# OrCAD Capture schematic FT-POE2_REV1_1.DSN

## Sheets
1 INDEX: title: 01-Index; rev: 1.1; note: 17 HaYetsira Street; note: Yokneam Illit, Israel 2069208
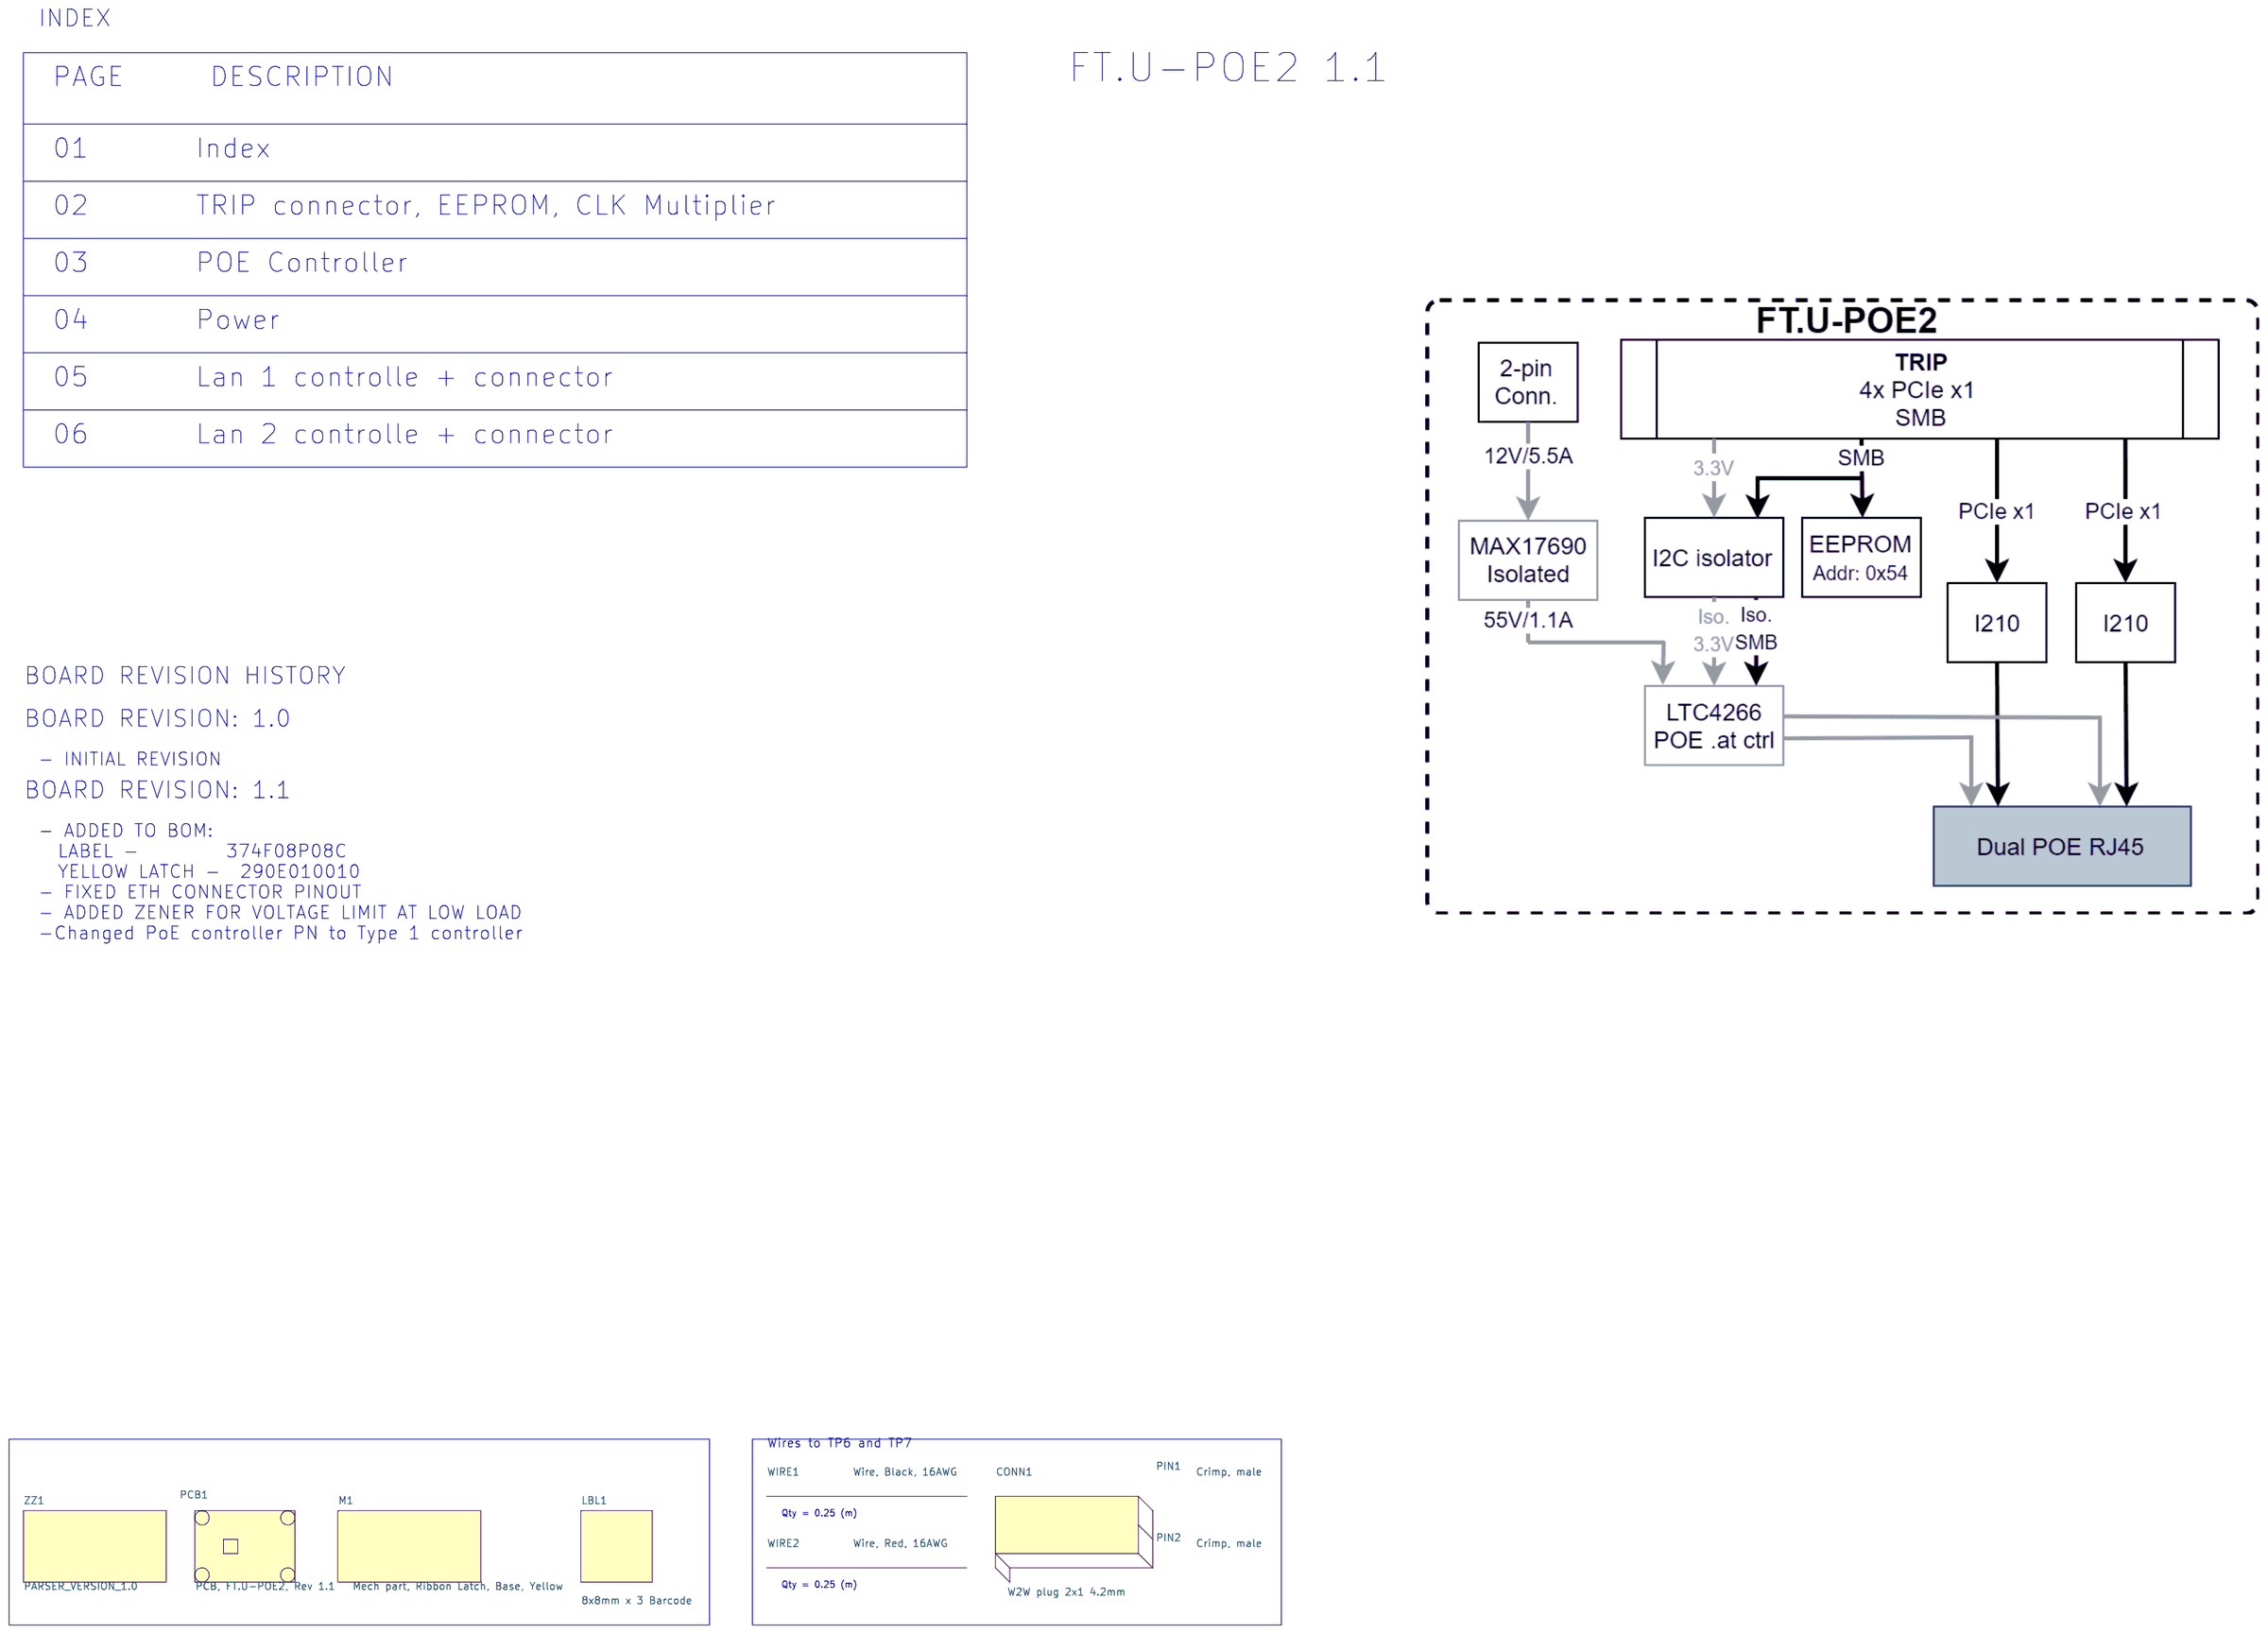
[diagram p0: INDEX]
2 TRIP/CLKMP: size A; title: 02-TRIP/CLKMP; rev: 1.0
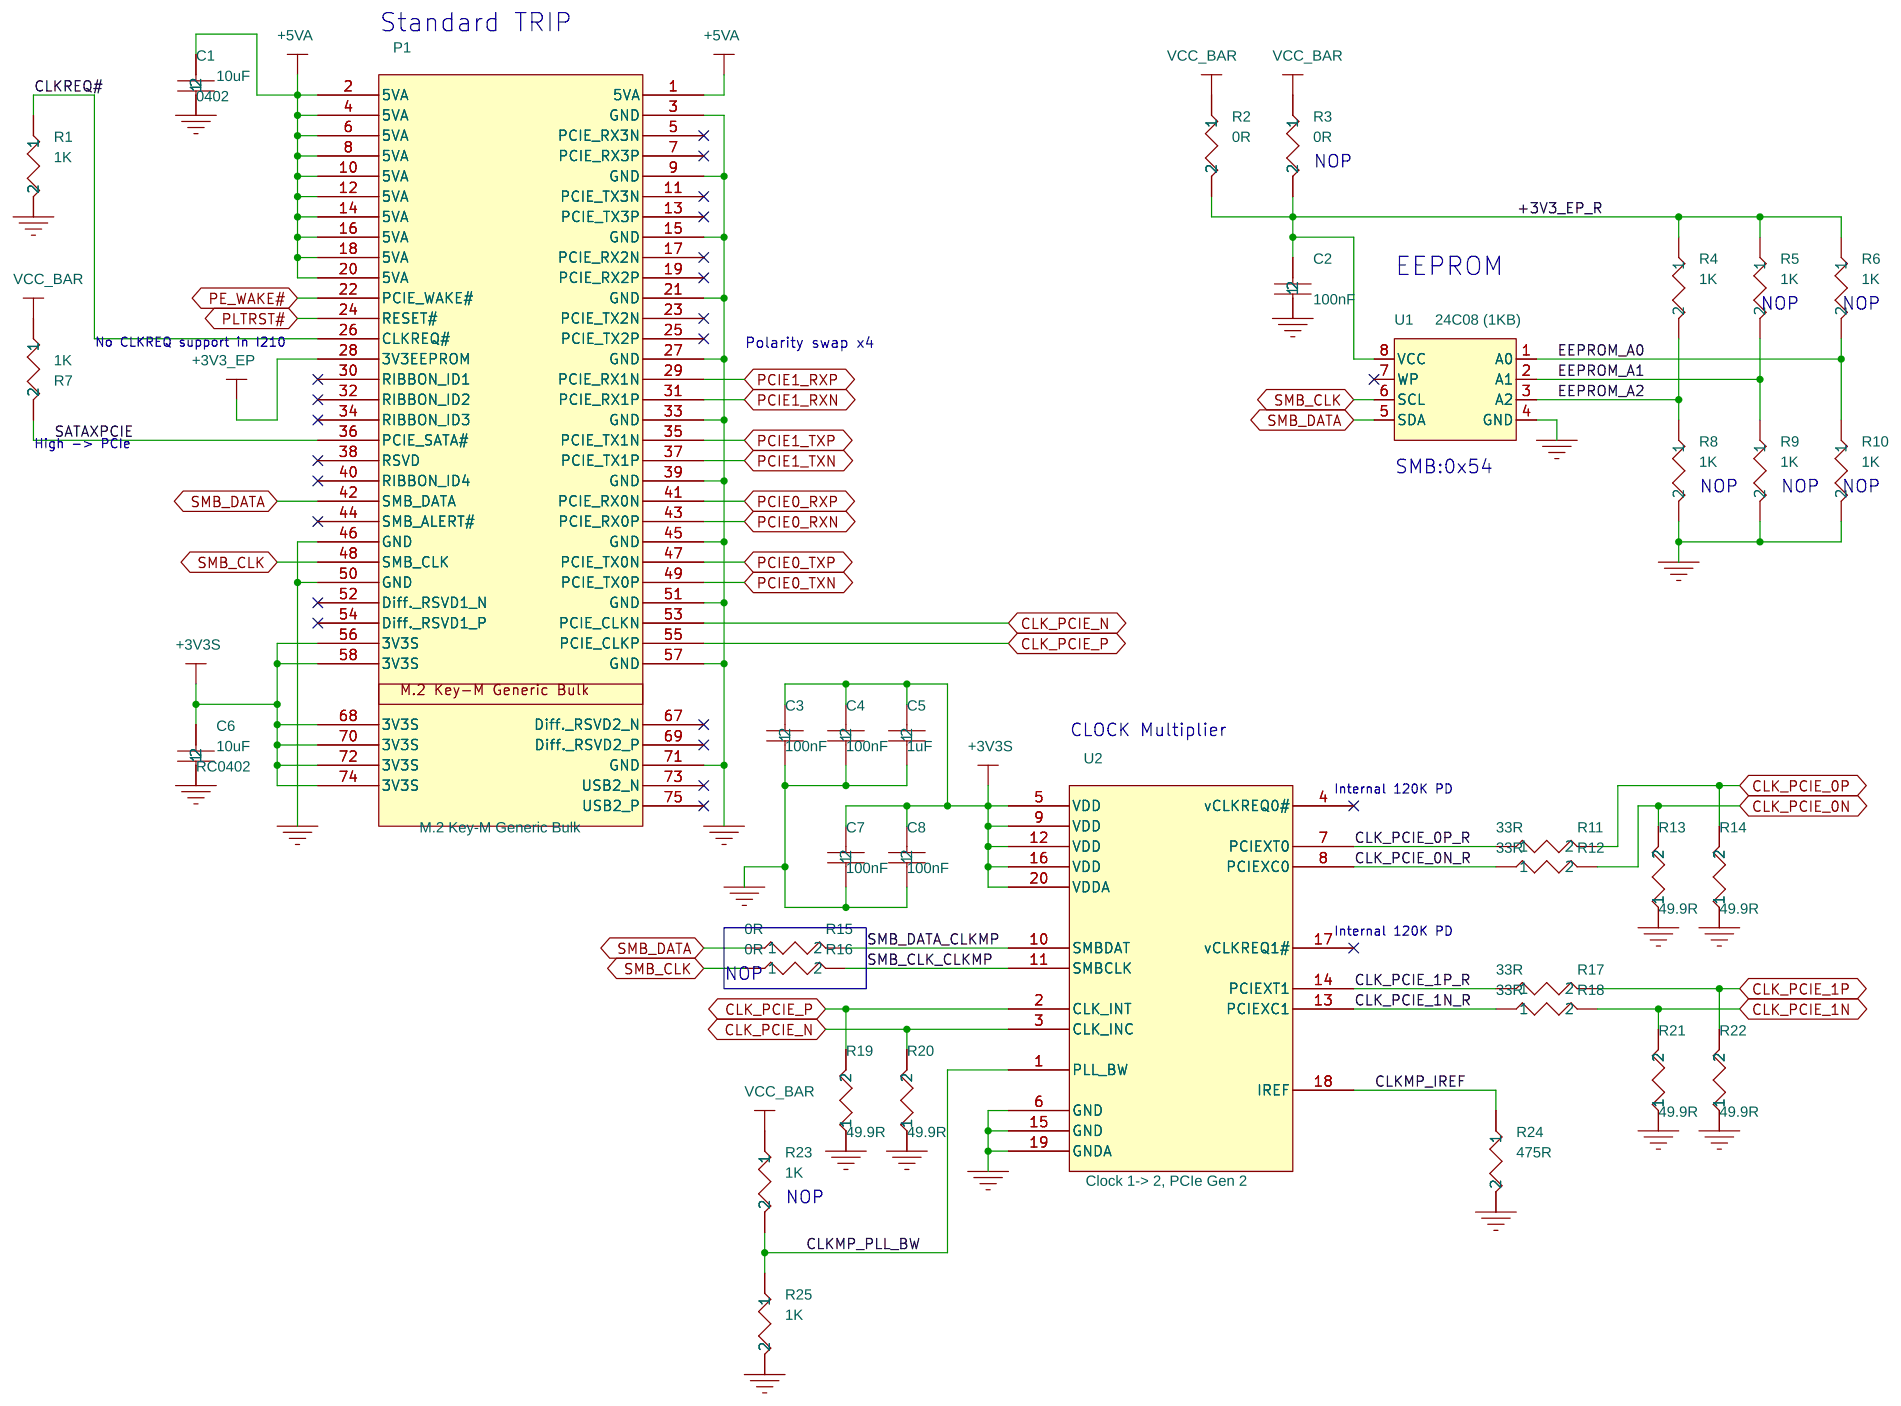
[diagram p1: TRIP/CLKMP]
3 POE/ISO: size A4; title: 03-POE/ISO; rev: 1.0
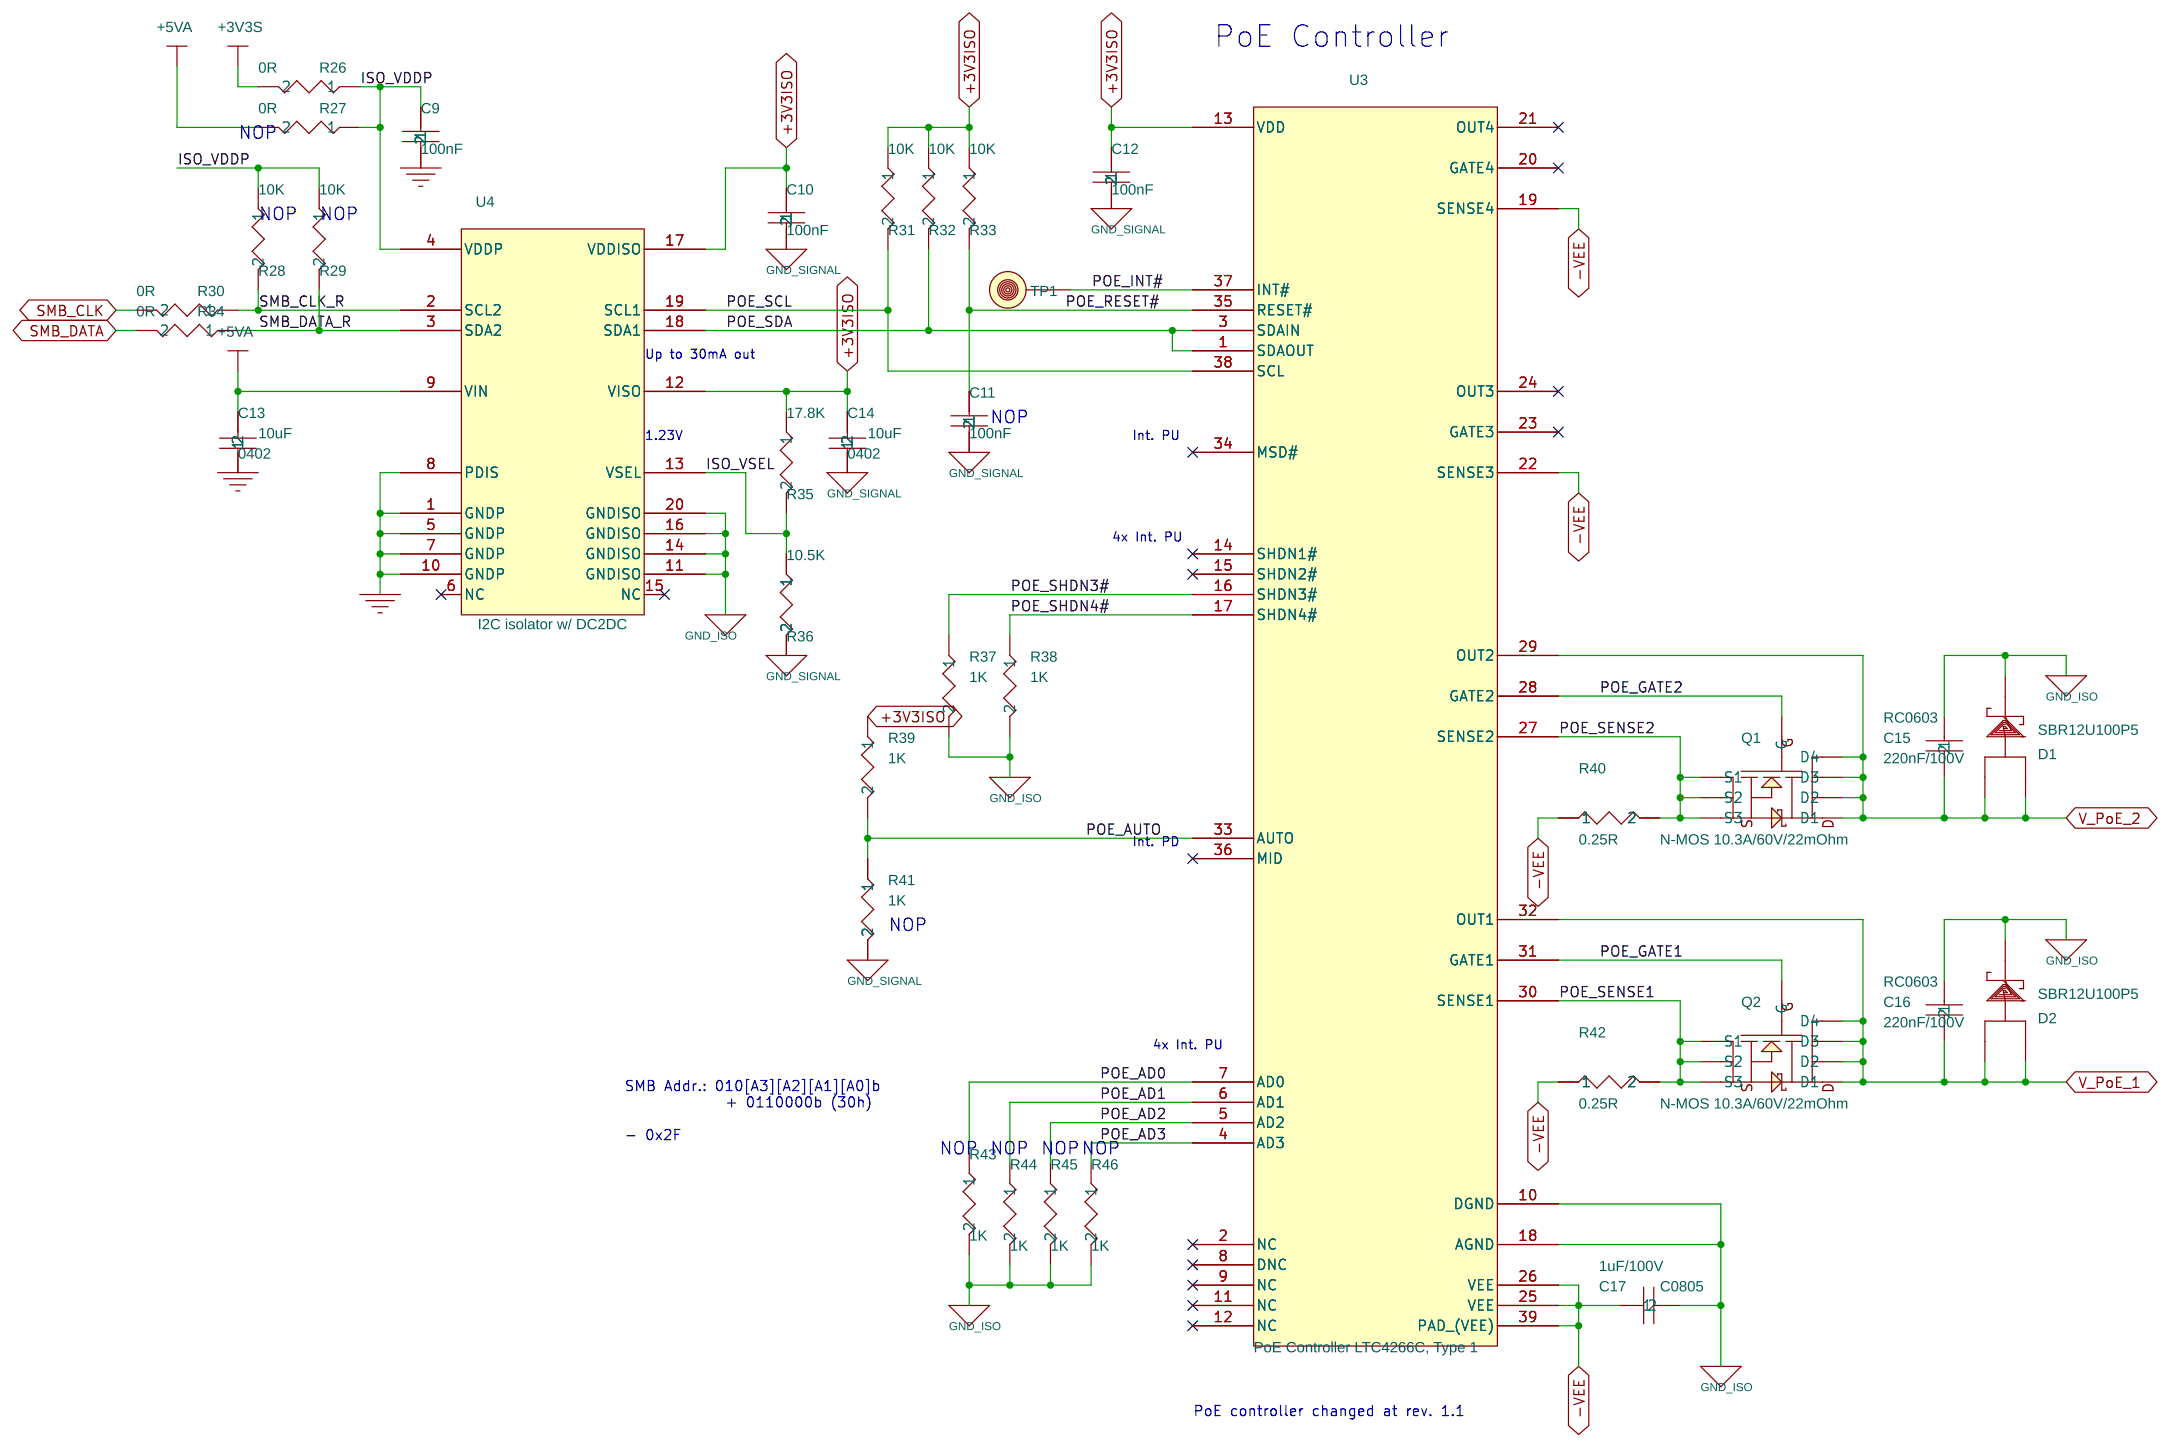
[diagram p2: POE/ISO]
4 POWER: size A4; title: 04-POWER; rev: 1.0
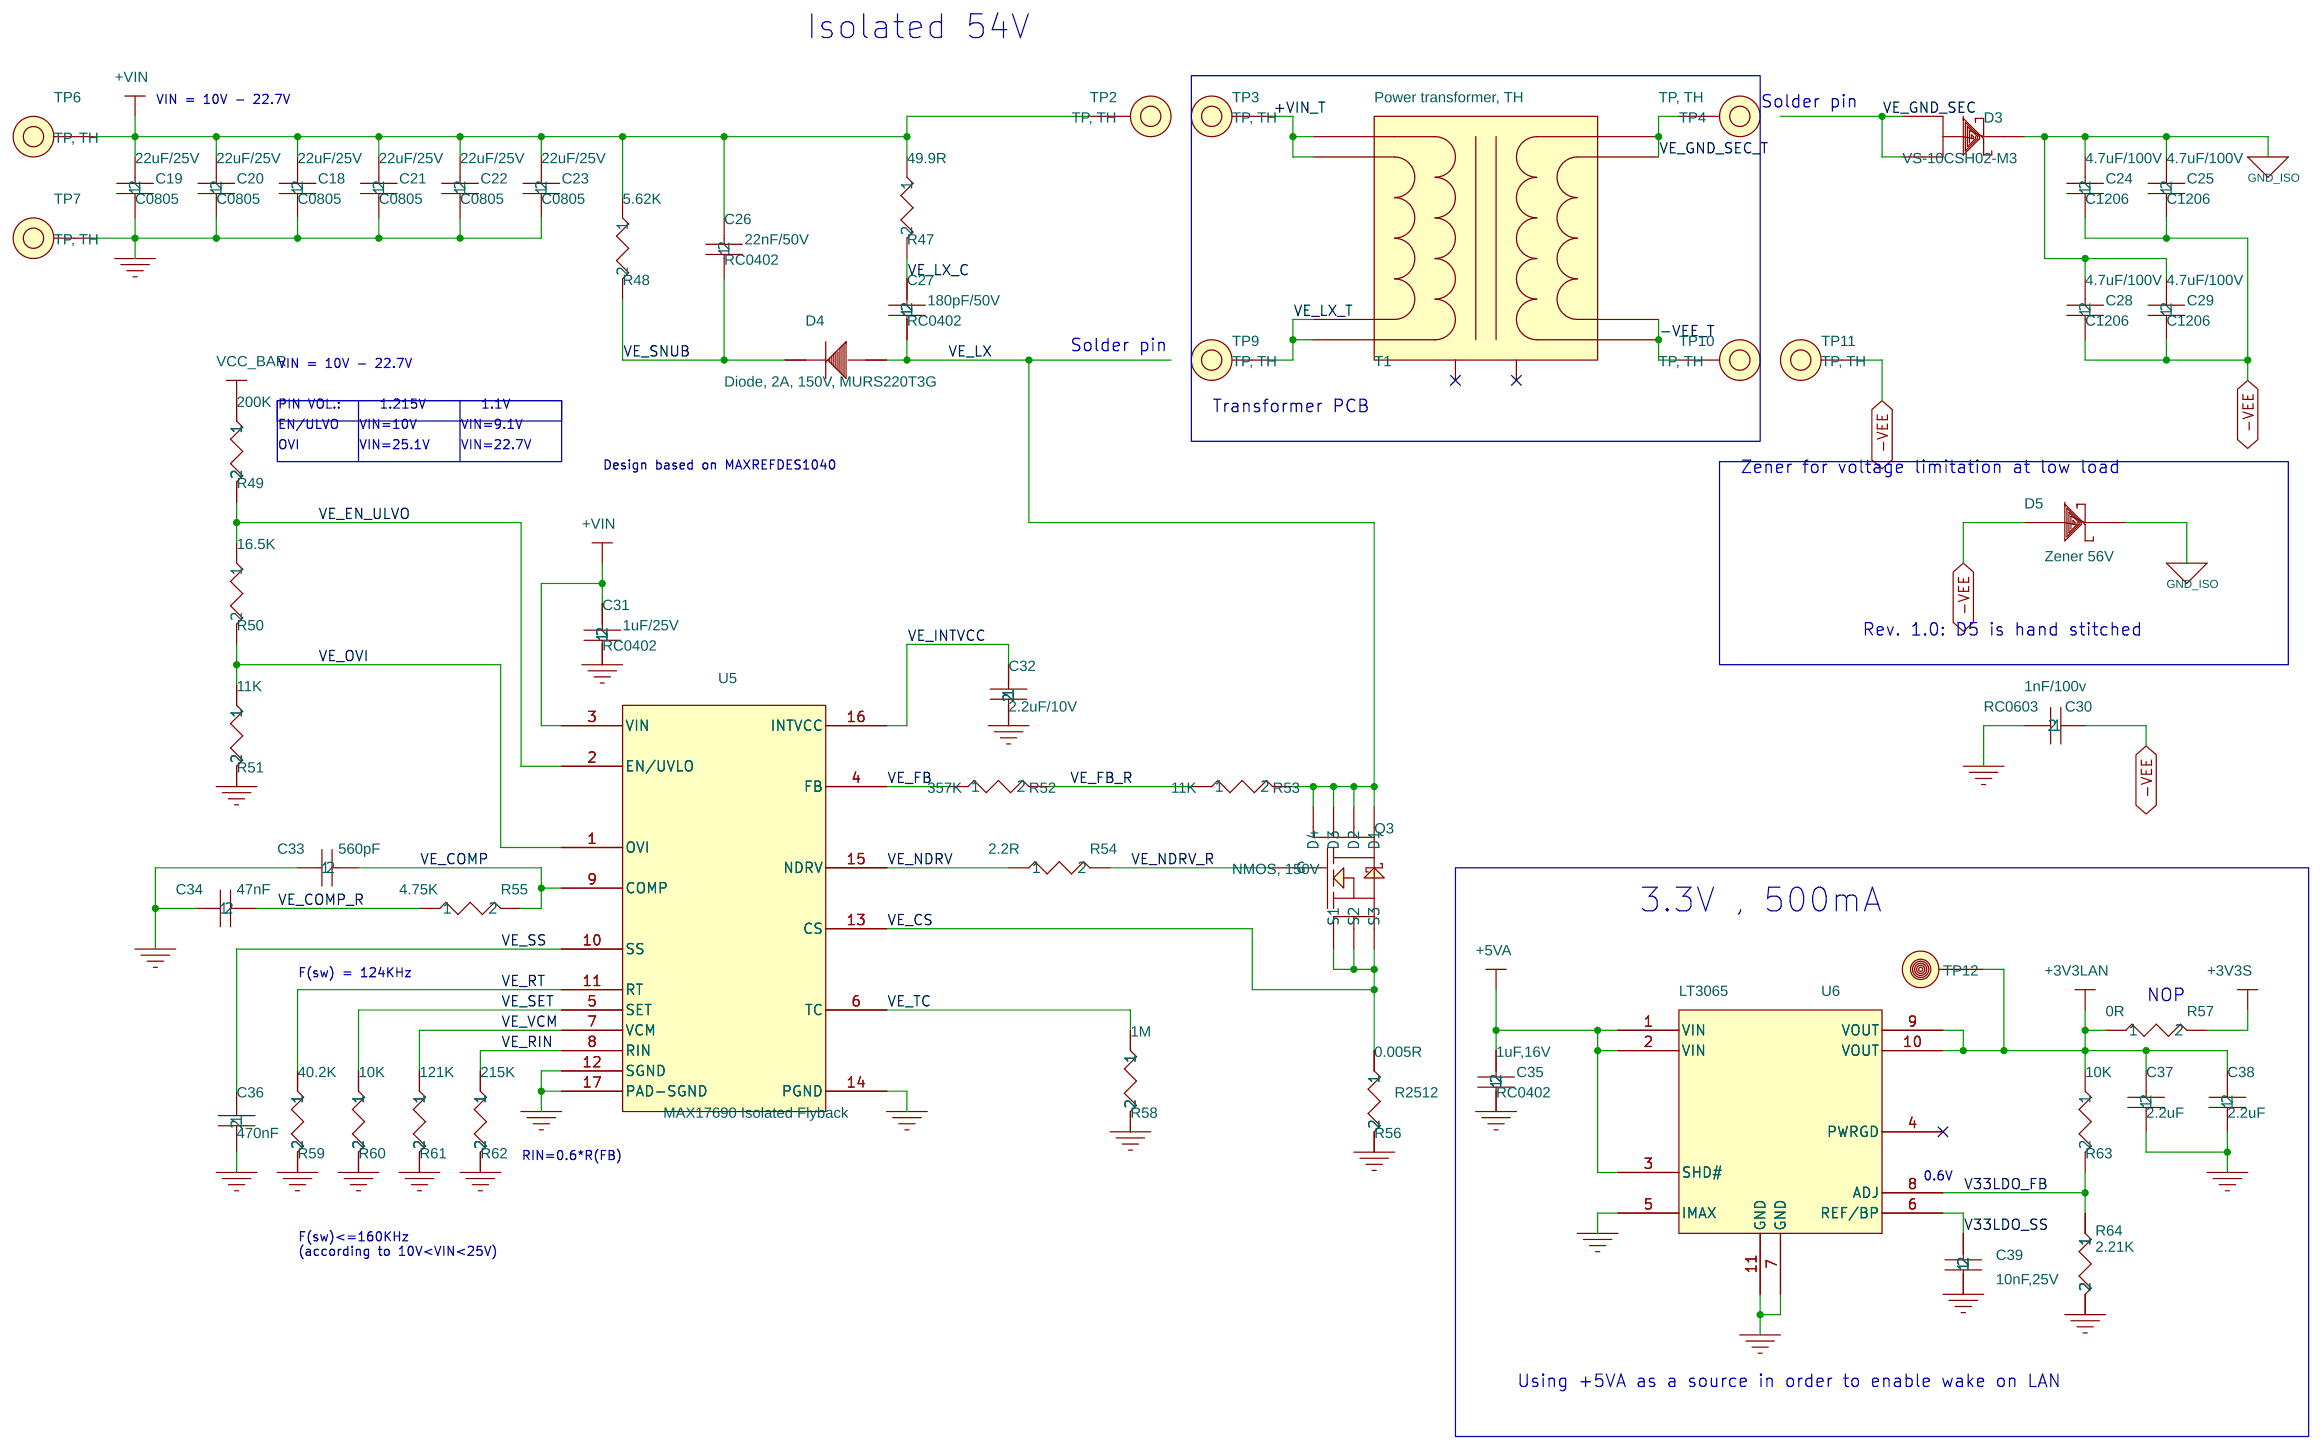
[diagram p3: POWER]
5 LAN1: size A3; title: 05-LAN1; rev: 1.0
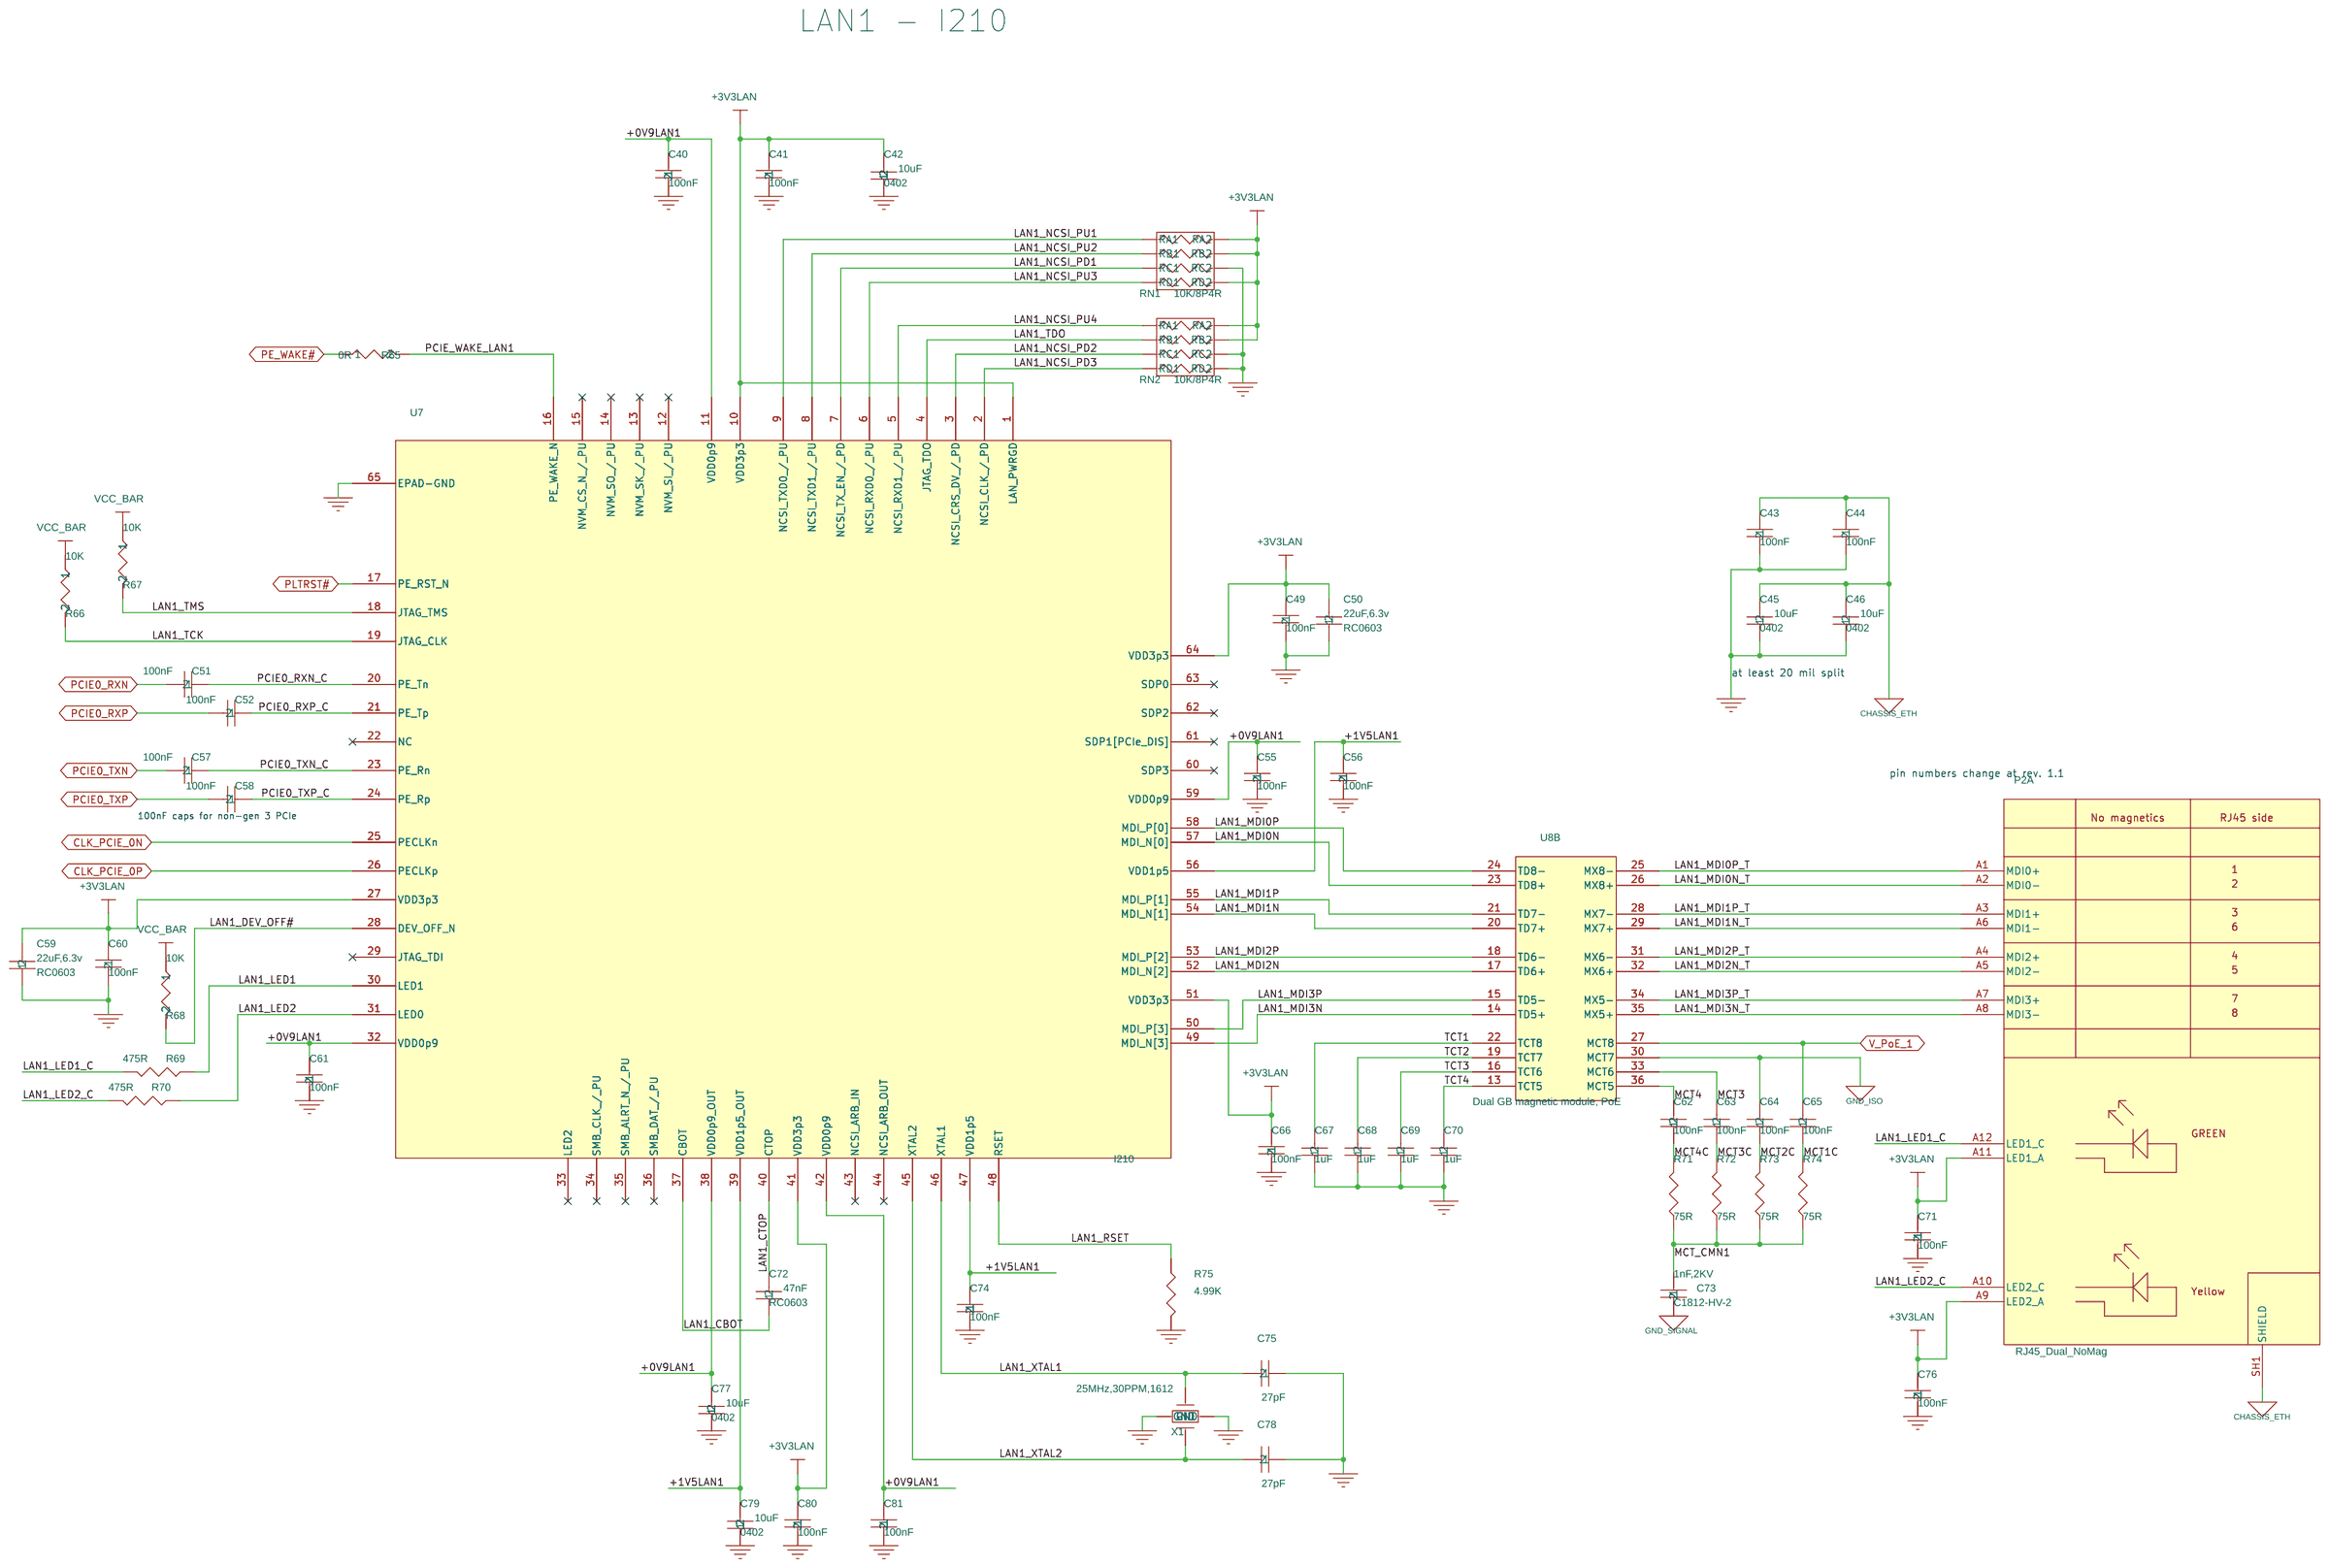
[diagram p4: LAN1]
6 LAN2: size A3; title: 06-LAN2; rev: 1.0
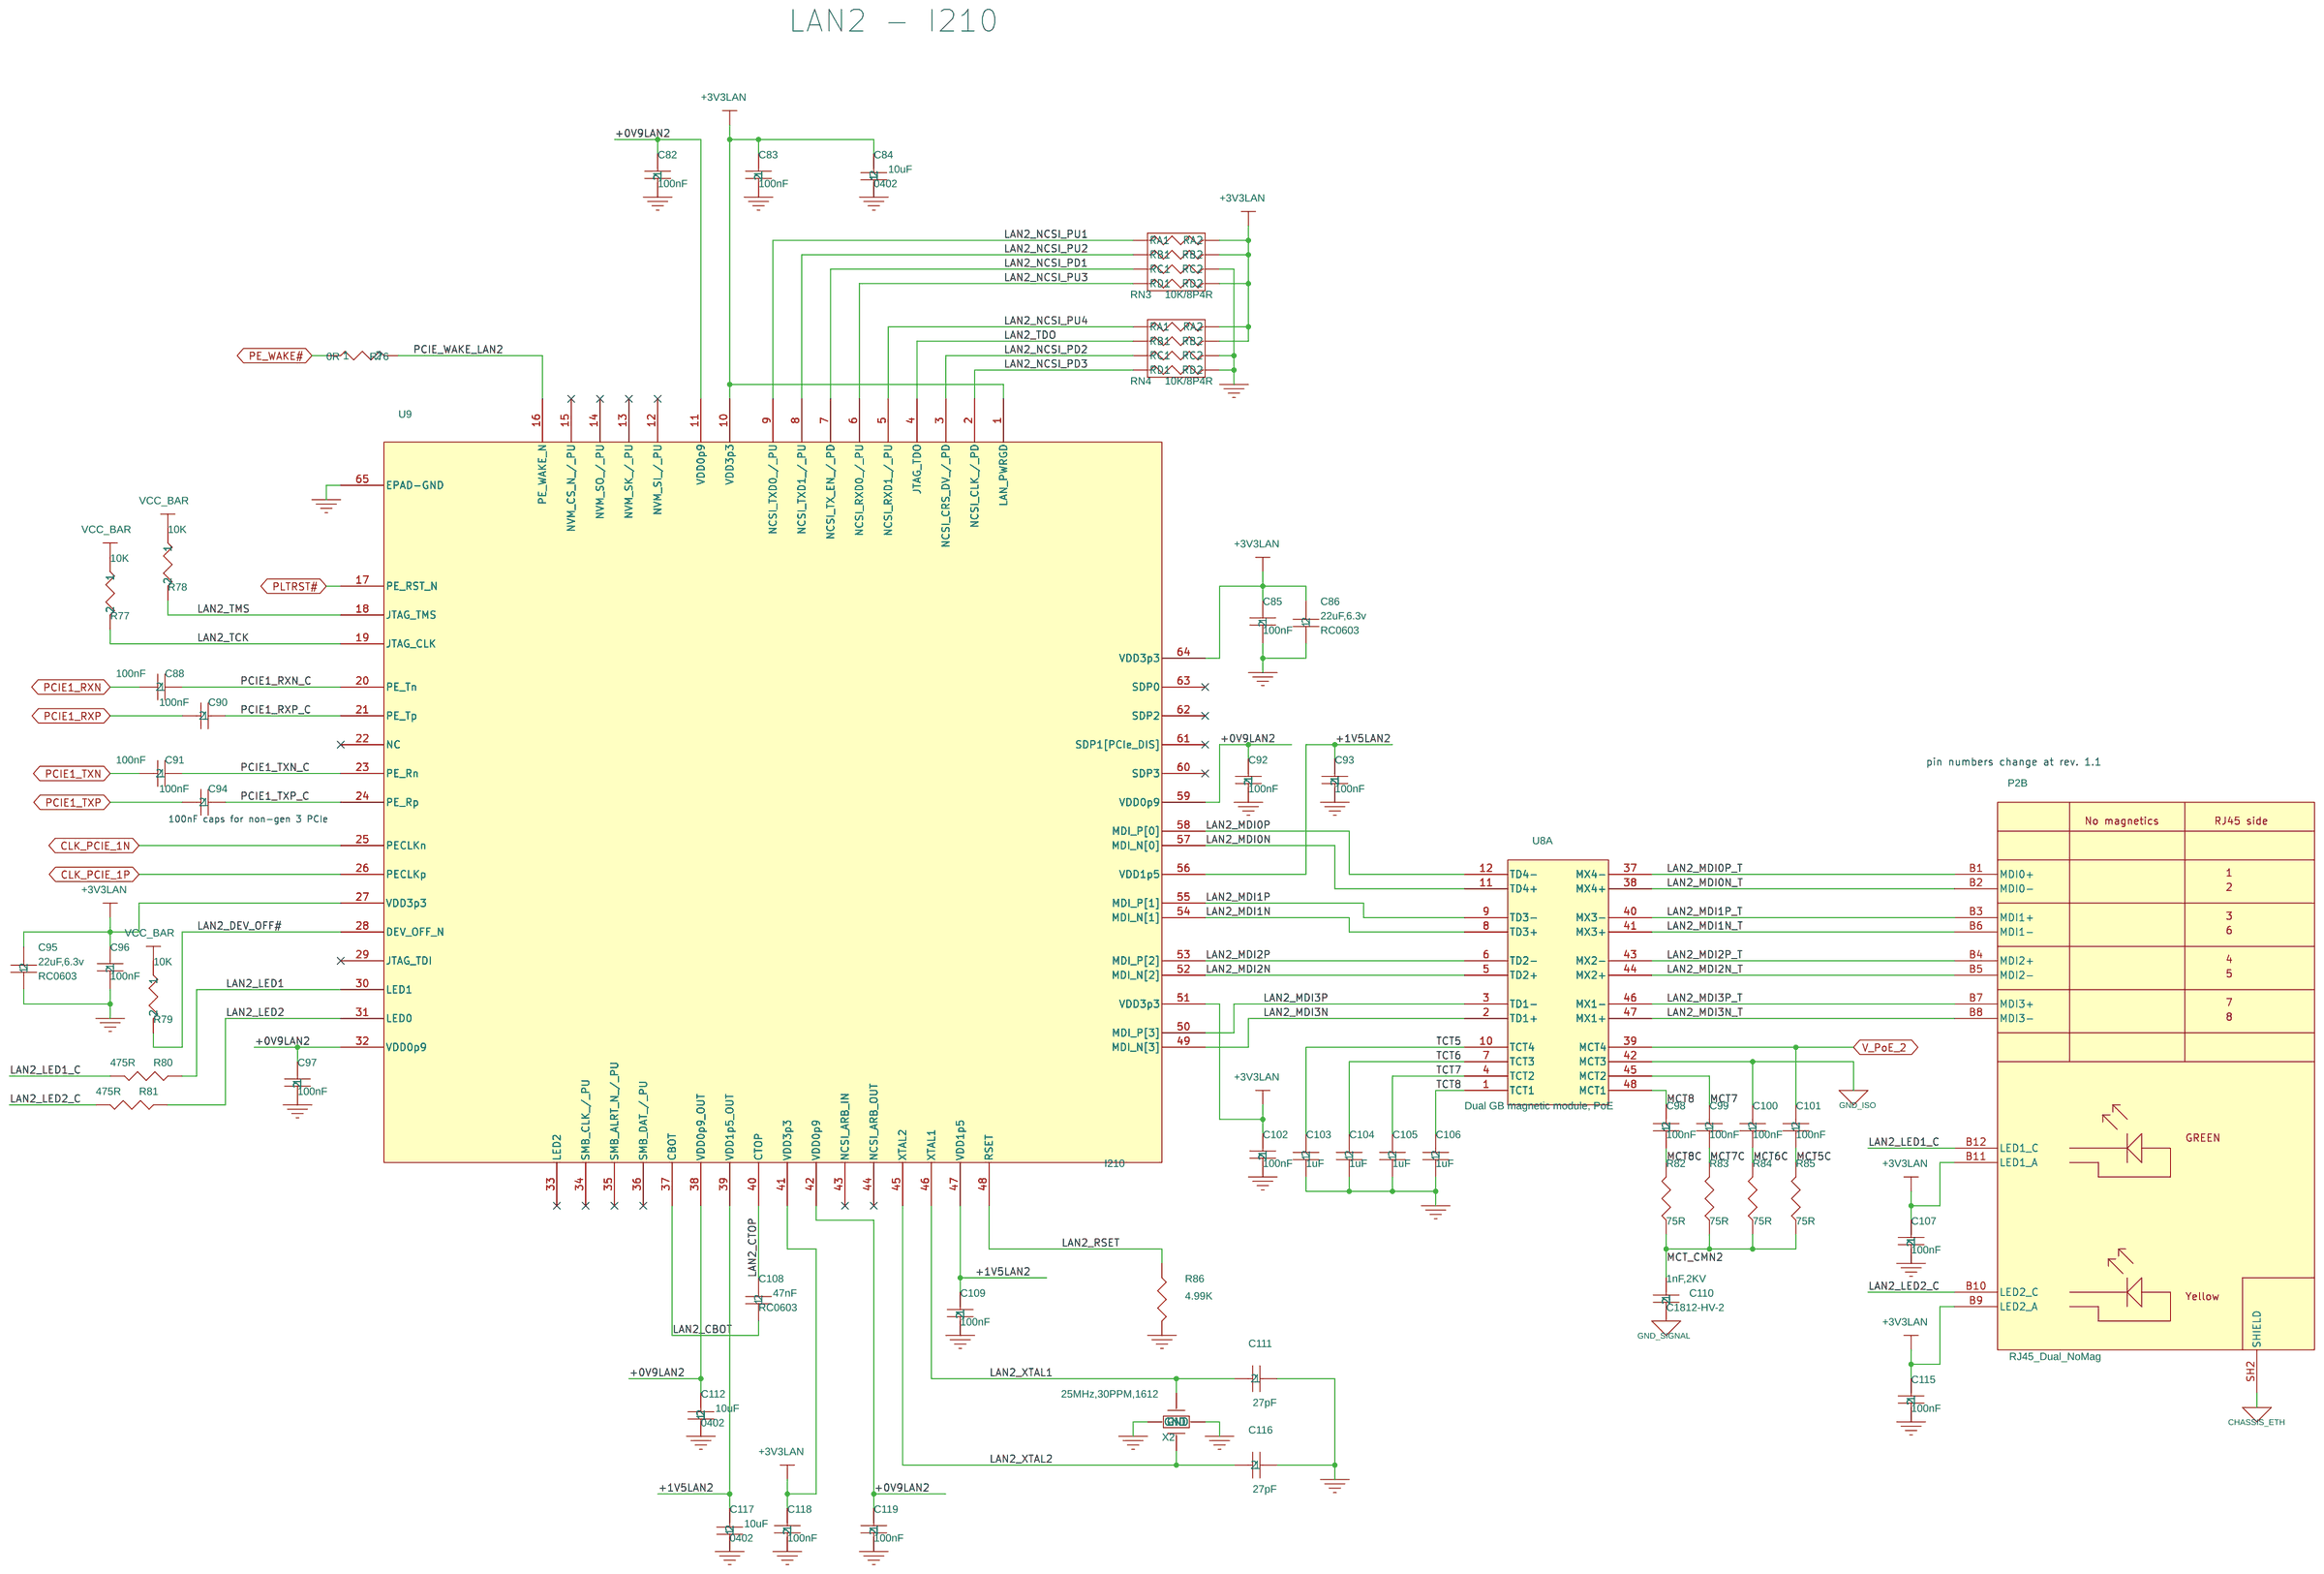
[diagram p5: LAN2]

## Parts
sheet INDEX
CONN1  W2W plug 2x1 4.2mm
LBL1  8x8mm x 3 Barcode  [LBL XYU]
M1  Mech part, Ribbon Latch, Base, Yellow
PCB1  PCB, FT.U-POE2, Rev 1.1
PIN1  Crimp, male
PIN2  Crimp, male
WIRE1  Wire, Black, 16AWG
WIRE2  Wire, Red, 16AWG
ZZ1  PARSER_VERSION_1.0
sheet LAN1
C40  100nF  [RC0402]
C41  100nF  [RC0402]
C42  10uF  [0402]
C43  100nF  [RC0402]
C44  100nF  [RC0402]
C45  10uF  [0402]
C46  10uF  [0402]
C49  100nF  [RC0402]
C50  22uF,6.3v  [RC0603]
C51  100nF  [RC0402]
C52  100nF  [RC0402]
C55  100nF  [RC0402]
C56  100nF  [RC0402]
C57  100nF  [RC0402]
C58  100nF  [RC0402]
C59  22uF,6.3v  [RC0603]
C60  100nF  [RC0402]
C61  100nF  [RC0402]
C62  100nF  [RC0402]
C63  100nF  [RC0402]
C64  100nF  [RC0402]
C65  100nF  [RC0402]
C66  100nF  [RC0402]
C67  1uF  [RC0402]
C68  1uF  [RC0402]
C69  1uF  [RC0402]
C70  1uF  [RC0402]
C71  100nF  [RC0402]
C72  47nF  [RC0603]
C73  1nF,2KV  [C1812-HV-2]
C74  100nF  [RC0402]
C75  27pF  [RC0402]
C76  100nF  [RC0402]
C77  10uF  [0402]
C78  27pF  [RC0402]
C79  10uF  [0402]
C80  100nF  [RC0402]
C81  100nF  [RC0402]
P2  RJ45_Dual_NoMag  (sections A,B)
R65  0R  [RC0402]
R66  10K  [RC0402]
R67  10K  [RC0402]
R68  10K  [RC0402]
R69  475R  [RC0402]
R70  475R  [RC0402]
R71  75R  [RC0402]
R72  75R  [RC0402]
R73  75R  [RC0402]
R74  75R  [RC0402]
R75  4.99K  [RC0402]
RN1  10K/8P4R  [RESNET8P0805]
RN2  10K/8P4R  [RESNET8P0805]
U7  I210  [QFN-64]
U8  Dual GB magnetic module, PoE  [TRLAN27_8x12_2x7_3]  (sections A,B)
X1  25MHz,30PPM,1612  [OSC1612]
sheet LAN2
C82  100nF  [RC0402]
C83  100nF  [RC0402]
C84  10uF  [0402]
C85  100nF  [RC0402]
C86  22uF,6.3v  [RC0603]
C88  100nF  [RC0402]
C90  100nF  [RC0402]
C91  100nF  [RC0402]
C92  100nF  [RC0402]
C93  100nF  [RC0402]
C94  100nF  [RC0402]
C95  22uF,6.3v  [RC0603]
C96  100nF  [RC0402]
C97  100nF  [RC0402]
C98  100nF  [RC0402]
C99  100nF  [RC0402]
C100  100nF  [RC0402]
C101  100nF  [RC0402]
C102  100nF  [RC0402]
C103  1uF  [RC0402]
C104  1uF  [RC0402]
C105  1uF  [RC0402]
C106  1uF  [RC0402]
C107  100nF  [RC0402]
C108  47nF  [RC0603]
C109  100nF  [RC0402]
C110  1nF,2KV  [C1812-HV-2]
C111  27pF  [RC0402]
C112  10uF  [0402]
C115  100nF  [RC0402]
C116  27pF  [RC0402]
C117  10uF  [0402]
C118  100nF  [RC0402]
C119  100nF  [RC0402]
R76  0R  [RC0402]
R77  10K  [RC0402]
R78  10K  [RC0402]
R79  10K  [RC0402]
R80  475R  [RC0402]
R81  475R  [RC0402]
R82  75R  [RC0402]
R83  75R  [RC0402]
R84  75R  [RC0402]
R85  75R  [RC0402]
R86  4.99K  [RC0402]
RN3  10K/8P4R  [RESNET8P0805]
RN4  10K/8P4R  [RESNET8P0805]
U9  I210  [QFN-64]
X2  25MHz,30PPM,1612  [OSC1612]
sheet POE/ISO
C9  100nF  [RC0402]
C10  100nF  [RC0402]
C11  100nF  [RC0402]
C12  100nF  [RC0402]
C13  10uF  [0402]
C14  10uF  [0402]
C15  220nF/100V  [RC0603]
C16  220nF/100V  [RC0603]
C17  1uF/100V  [C0805]
D1  SBR12U100P5  [TO-277A]
D2  SBR12U100P5  [TO-277A]
Q1  N-MOS 10.3A/60V/22mOhm  [PowerpakSO-8]
Q2  N-MOS 10.3A/60V/22mOhm  [PowerpakSO-8]
R26  0R  [RC0402]
R27  0R  [RC0402]
R28  10K  [RC0402]
R29  10K  [RC0402]
R30  0R  [RC0402]
R31  10K  [RC0402]
R32  10K  [RC0402]
R33  10K  [RC0402]
R34  0R  [RC0402]
R35  17.8K  [RC0402]
R36  10.5K  [RC0402]
R37  1K  [RC0402]
R38  1K  [RC0402]
R39  1K  [RC0402]
R40  0.25R  [RC0603]
R41  1K  [RC0402]
R42  0.25R  [RC0603]
R43  1K  [RC0402]
R44  1K  [RC0402]
R45  1K  [RC0402]
R46  1K  [RC0402]
TP1  TP
U3  PoE Controller LTC4266C, Type 1  [MO-220WHKD]
U4  I2C isolator w/ DC2DC  [SSOP-20]
sheet POWER
C18  22uF/25V  [C0805]
C19  22uF/25V  [C0805]
C20  22uF/25V  [C0805]
C21  22uF/25V  [C0805]
C22  22uF/25V  [C0805]
C23  22uF/25V  [C0805]
C24  4.7uF/100V  [C1206]
C25  4.7uF/100V  [C1206]
C26  22nF/50V  [RC0402]
C27  180pF/50V  [RC0402]
C28  4.7uF/100V  [C1206]
C29  4.7uF/100V  [C1206]
C30  1nF/100v  [RC0603]
C31  1uF/25V  [RC0402]
C32  2.2uF/10V  [RC0402]
C33  560pF  [RC0402]
C34  47nF  [RC0402]
C35  1uF,16V  [RC0402]
C36  470nF  [RC0402]
C37  2.2uF  [RC0402]
C38  2.2uF  [RC0402]
C39  10nF,25V  [RC0402]
D3  VS-10CSH02-M3  [TO-277A]
D4  Diode, 2A, 150V, MURS220T3G  [DO-214AA]
D5  Zener 56V  [SOD-323]
Q3  NMOS, 150V  [PowerpakSO-8]
R47  49.9R  [RC0402]
R48  5.62K  [RC0402]
R49  200K  [RC0402]
R50  16.5K  [RC0402]
R51  11K  [RC0402]
R52  357K  [RC0402]
R53  11K  [RC0402]
R54  2.2R  [RC0402]
R55  4.75K  [RC0402]
R56  0.005R  [R2512]
R57  0R  [RC0402]
R58  1M  [RC0402]
R59  40.2K  [RC0402]
R60  10K  [RC0402]
R61  121K  [RC0402]
R62  215K  [RC0402]
R63  10K  [RC0402]
R64  2.21K  [RC0402]
T1  Power transformer, TH  [TRPOW23x15x24]
TP2  TP, TH  [TPRTH2m]
TP3  TP, TH  [TPRTH2m]
TP4  TP, TH  [TPRTH2m]
TP6  TP, TH  [TPRTH2m]
TP7  TP, TH  [TPRTH2m]
TP9  TP, TH  [TPRTH2m]
TP10  TP, TH  [TPRTH2m]
TP11  TP, TH  [TPRTH2m]
TP12  TP
U5  MAX17690 Isolated Flyback  [MO-220WEED-2]
U6  LT3065  [DFN3x3-10]
sheet TRIP/CLKMP
C1  10uF  [0402]
C2  100nF  [RC0402]
C3  100nF  [RC0402]
C4  100nF  [RC0402]
C5  1uF  [RC0402]
C6  10uF  [RC0402]
C7  100nF  [RC0402]
C8  100nF  [RC0402]
P1  M.2 Key-M Generic Bulk  [NGFF67P8HMkeySM]
R1  1K  [RC0402]
R2  0R  [RC0402]
R3  0R  [RC0402]
R4  1K  [RC0402]
R5  1K  [RC0402]
R6  1K  [RC0402]
R7  1K  [RC0402]
R8  1K  [RC0402]
R9  1K  [RC0402]
R10  1K  [RC0402]
R11  33R  [RC0402]
R12  33R  [RC0402]
R13  49.9R  [RC0402]
R14  49.9R  [RC0402]
R15  0R  [RC0402]
R16  0R  [RC0402]
R17  33R  [RC0402]
R18  33R  [RC0402]
R19  49.9R  [RC0402]
R20  49.9R  [RC0402]
R21  49.9R  [RC0402]
R22  49.9R  [RC0402]
R23  1K  [RC0402]
R24  475R  [RC0402]
R25  1K  [RC0402]
U1  24C08 (1KB)  [MO-229VCED-2]
U2  Clock 1-> 2, PCIe Gen 2  [TSSOP-20]

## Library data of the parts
CONN1 = W2W_plug_2x1_4_0.2mm: CLABCONF0: FT.U-POE2; P/N: 180A00201
LBL1 = Label_8x8mm_x_3_for_Barcode: CLABCONF0: FT.U-POE2
M1 = PARSER_VERSION_1_0.0: CLABCONF0: FT.U-POE2; P/N: 290E010010
PCB1 = SBC-iHSW_Rev_1.0: CLABCONF0: FT.U-POE2; P/N: 188C03551U
PIN1 PIN2 = Crimp,_male: CLABCONF0: FT.U-POE2; P/N: 197A00100
WIRE1 = Wire,_Black,_16AWG: CLABCONF0: 0.25#409M02001 = FT.U-POE2; CLABUNIT: m; P/N: 409M02001
WIRE2 = Wire,_Black,_16AWG: CLABCONF0: 0.25#409M03001 = FT.U-POE2; CLABUNIT: m; P/N: 409M03001
ZZ1 = PARSER_VERSION_1.0: CLABCONF0: FT.U-POE2
C40 C102 = 15pF,_50V,_NPO,_5%,_0402_15: CLABCONF0: FT.U-POE2; P/N: 151B10400S
C4 C41 C118 = 15pF,_50V,_NPO,_5%,_0402: CLABCONF0: FT.U-POE2; P/N: 151B10400S
C14 C42 = 100nF,_10V,_X7R,_10%,_0402_6: CLABCONF0: FT.U-POE2; P/N: 151B10600S
C43 C93 = 15pF,_50V,_NPO,_5%,_0402_16: CLABCONF0: FT.U-POE2; P/N: 151B10400S
C44 C99 = 15pF,_50V,_NPO,_5%,_0402_7: CLABCONF0: FT.U-POE2; P/N: 151B10400S
C6 C45 C112 = 100nF,_10V,_X7R,_10%,_0402_2: CLABCONF0: FT.U-POE2; P/N: 151B10600S
C46 = 100nF,_10V,_X7R,_10%,_0402_14: CLABCONF0: FT.U-POE2; P/N: 151B10600S
C49 C83 = 15pF,_50V,_NPO,_5%,_0402_14: CLABCONF0: FT.U-POE2; P/N: 151B10400S
C50 = 100nF,_10V,_X7R,_10%,_0402_12: CLABCONF0: FT.U-POE2; P/N: 151B22610S
C51 = 100nF,_10V,_X7R,_10%,_0402_13: CLABCONF0: FT.U-POE2; P/N: 151B10400S
C52 = 100nF,_10V,_X7R,_10%,_0402_7: CLABCONF0: FT.U-POE2; P/N: 151B10400S
C55 C92 = 15pF,_50V,_NPO,_5%,_0402_8: CLABCONF0: FT.U-POE2; P/N: 151B10400S
C56 C82 = 15pF,_50V,_NPO,_5%,_0402_13: CLABCONF0: FT.U-POE2; P/N: 151B10400S
C57 = 100nF,_10V,_X7R,_10%,_0402_16: CLABCONF0: FT.U-POE2; P/N: 151B10400S
C58 = 100nF,_10V,_X7R,_10%,_0402_9: CLABCONF0: FT.U-POE2; P/N: 151B10400S
C59 C95 = 100nF,_10V,_X7R,_10%,_0402_1: CLABCONF0: FT.U-POE2; P/N: 151B22610S
C7 C60 C101 = 15pF,_50V,_NPO,_5%,_0402_2: CLABCONF0: FT.U-POE2; P/N: 151B10400S
C61 C109 = 15pF,_50V,_NPO,_5%,_0402_6: CLABCONF0: FT.U-POE2; P/N: 151B10400S
C62 C107 = 15pF,_50V,_NPO,_5%,_0402_10: CLABCONF0: FT.U-POE2; P/N: 151B10400S
C63 = 15pF,_50V,_NPO,_5%,_0402_19: CLABCONF0: FT.U-POE2; P/N: 151B10400S
C64 C85 = 15pF,_50V,_NPO,_5%,_0402_11: CLABCONF0: FT.U-POE2; P/N: 151B10400S
C65 = 15pF,_50V,_NPO,_5%,_0402_20: CLABCONF0: FT.U-POE2; P/N: 151B10400S
C66 C96 = 15pF,_50V,_NPO,_5%,_0402_17: CLABCONF0: FT.U-POE2; P/N: 151B10400S
C35 C67 = 100nF,_10V,_X7R,_10%,_0402_5: CLABCONF0: FT.U-POE2; P/N: 151C10500S
C68 = 100nF,_10V,_X7R,_10%,_0402_15: CLABCONF0: FT.U-POE2; P/N: 151C10500S
C69 C103 = 100nF,_10V,_X7R,_10%,_0402_4: CLABCONF0: FT.U-POE2; P/N: 151C10500S
C70 = 100nF,_10V,_X7R,_10%,_0402_11: CLABCONF0: FT.U-POE2; P/N: 151C10500S
C71 C98 = 15pF,_50V,_NPO,_5%,_0402_9: CLABCONF0: FT.U-POE2; P/N: 151B10400S
C72 = 100nF,_10V,_X7R,_10%,_0402_10: CLABCONF0: FT.U-POE2; P/N: 151C47310S
C73 = 100nF,_10V,_X7R,_10%,_0402: CLABCONF0: FT.U-POE2; P/N: 151J10250S
C74 C115 = 15pF,_50V,_NPO,_5%,_0402_18: CLABCONF0: FT.U-POE2; P/N: 151B10400S
C75 = 15pF,_50V,_NPO,_5%,_0402_5: CLABCONF0: FT.U-POE2; P/N: 151D27000S
C2 C76 C119 = 15pF,_50V,_NPO,_5%,_0402_4: CLABCONF0: FT.U-POE2; P/N: 151B10400S
C77 = 100nF,_10V,_X7R,_10%,_0402_3: CLABCONF0: FT.U-POE2; P/N: 151B10600S
C78 C111 = 15pF,_50V,_NPO,_5%,_0402_3: CLABCONF0: FT.U-POE2; P/N: 151D27000S
C79 C84 = 100nF,_10V,_X7R,_10%,_0402_8: CLABCONF0: FT.U-POE2; P/N: 151B10600S
C3 C80 = 15pF,_50V,_NPO,_5%,_0402_1: CLABCONF0: FT.U-POE2; P/N: 151B10400S
C81 C97 = 15pF,_50V,_NPO,_5%,_0402_12: CLABCONF0: FT.U-POE2; P/N: 151B10400S
P2 = RJ45_Dual_NoMag_1: CLABCONF0: FT.U-POE2; P/N: 180K02402; Color: Default; Location X-Coordinate: 0; Location Y-Coordinate: 0; Power Pins Visible: False; Primitive: DEFAULT
R65 R76 = 0R_2: CLABCONF0: FT.U-POE2; OriginalSymbolOrigin: 100uF
R33 R66 R79 = 0R_1: CLABCONF0: FT.U-POE2; P/N: 161C10021S
R32 R67 R78 = 0R: CLABCONF0: FT.U-POE2; P/N: 161C10021S
R31 R68 R77 = 0R_3: CLABCONF0: FT.U-POE2; P/N: 161C10021S
R69 R70 R80 R81 = RESISTOR: CLABCONF0: FT.U-POE2; P/N: 161C47501S
R71-R74 R82-R85 = RESISTOR: CLABCONF0: FT.U-POE2; P/N: 161C75R01S
R75 R86 = RESISTOR: CLABCONF0: FT.U-POE2; P/N: 161C49911S
RN1-RN4 = RN,10K,8P4R@0805: CLABCONF0: FT.U-POE2
U7 U9 = IC,_I211_I210_,LAN_CONTROLLER: CLABCONF0: FT.U-POE2; P/N: 116B00071S
U8 = 1000Base_magnetic_module,_PoE_2: CLABCONF0: FT.U-POE2; Color: Default; Location X-Coordinate: 0; Location Y-Coordinate: 0; P/N: 147E00001S; Power Pins Visible: False; Primitive: DEFAULT
X1 X2 = TMP_133032: CLABCONF0: FT.U-POE2; P/N: 141B25604S
C86 = 100nF,_10V,_X7R,_10%,_0402_13: CLABCONF0: FT.U-POE2; P/N: 151B22610S
C88 = 100nF,_10V,_X7R,_10%,_0402_5: CLABCONF0: FT.U-POE2; P/N: 151B10400S
C90 = 100nF,_10V,_X7R,_10%,_0402_14: CLABCONF0: FT.U-POE2; P/N: 151B10400S
C91 = 100nF,_10V,_X7R,_10%,_0402_6: CLABCONF0: FT.U-POE2; P/N: 151B10400S
C94 = 100nF,_10V,_X7R,_10%,_0402_3: CLABCONF0: FT.U-POE2; P/N: 151B10400S
C100 = 15pF,_50V,_NPO,_5%,_0402_5: CLABCONF0: FT.U-POE2; P/N: 151B10400S
C104 = 100nF,_10V,_X7R,_10%,_0402_7: CLABCONF0: FT.U-POE2; P/N: 151C10500S
C105 = 100nF,_10V,_X7R,_10%,_0402_9: CLABCONF0: FT.U-POE2; P/N: 151C10500S
C106 = 100nF,_10V,_X7R,_10%,_0402_10: CLABCONF0: FT.U-POE2; P/N: 151C10500S
C108 = 100nF,_10V,_X7R,_10%,_0402_12: CLABCONF0: FT.U-POE2; P/N: 151C47310S
C110 = 100nF,_10V,_X7R,_10%,_0402_11: CLABCONF0: FT.U-POE2; P/N: 151J10250S
C116 = 15pF,_50V,_NPO,_5%,_0402_1: CLABCONF0: FT.U-POE2; P/N: 151D27000S
C1 C13 C117 = 100nF,_10V,_X7R,_10%,_0402: CLABCONF0: FT.U-POE2; P/N: 151B10600S
C9 = 100nF,_10V,_X7R,_10%,_0402_1: CLABCONF0: FT.U-POE2
C10 = 100nF,_10V,_X7R,_10%,_0402_5: CLABCONF0: FT.U-POE2
C11 = 15pF,_50V,_NPO,_5%,_0402: CLABCONF0: NOP; P/N: 151B10400S
C12 = 100nF,_10V,_X7R,_10%,_0402_3: CLABCONF0: FT.U-POE2
C15 = 100nF,_10V,_X7R,_10%,_0402_2: CLABCONF0: FT.U-POE2; P/N: 151E22410S
C16 = 100nF,_10V,_X7R,_10%,_0402_4: CLABCONF0: FT.U-POE2; P/N: 151E22410S
C17 = 100nF,_10V,_X7R,_10%,_0402_7: CLABCONF0: FT.U-POE2; P/N: 151E10520S
D1 D2 = Diode_,SBR12U100P5: CLABCONF0: FT.U-POE2; P/N: 130E12000S
Q1 Q2 = FDMS7682_0: CLABCONF0: FT.U-POE2; P/N: 131D78500I
R26 = 10K,1%,0402,1_16W_12: CLABCONF0: FT.U-POE2; P/N: 161C00005S
R27 = 10K,1%,0402,1_16W_5: CLABCONF0: NOP; P/N: 161C00005S
R28 = 0R_5: CLABCONF0: NOP; P/N: 161C10021S
R29 = 0R_4: CLABCONF0: NOP; P/N: 161C10021S
R30 = 10K,1%,0402,1_16W_13: CLABCONF0: FT.U-POE2; P/N: 161C00005S
R34 = 10K,1%,0402,1_16W_7: CLABCONF0: FT.U-POE2; P/N: 161C00005S
R35 = 0R_6: CLABCONF0: FT.U-POE2; P/N: 161C17821S
R36 = 0R_2: CLABCONF0: FT.U-POE2; P/N: 161C10521S
R37 = 10K,1%,0402,1_16W_2: CLABCONF0: FT.U-POE2; P/N: 161C10011S
R38 = 10K,1%,0402,1_16W_9: CLABCONF0: FT.U-POE2; P/N: 161C10011S
R39 = 10K,1%,0402,1_16W: CLABCONF0: FT.U-POE2; P/N: 161C10011S
R40 = 10K,1%,0402,1_16W_11: CLABCONF0: FT.U-POE2; P/N: 161DR2501S
R41 = 10K,1%,0402,1_16W_1: CLABCONF0: NOP; P/N: 161C10011S
R42 = 10K,1%,0402,1_16W_8: CLABCONF0: FT.U-POE2; P/N: 161DR2501S
R43 = 10K,1%,0402,1_16W_6: CLABCONF0: NOP; P/N: 161C10011S
R44 = 10K,1%,0402,1_16W_3: CLABCONF0: NOP; P/N: 161C10011S
R45 = 10K,1%,0402,1_16W_10: CLABCONF0: NOP; P/N: 161C10011S
R46 = 10K,1%,0402,1_16W_4: CLABCONF0: NOP; P/N: 161C10011S
TP1 TP12 = TP_SMT: CLABCONF0: NOP
U3 = PoE_Controller_LTC4266C__4: CLABCONF0: FT.U-POE2; P/N: 116B00171S
U4 = I2C_isolator_w_DC2DC: CLABCONF0: FT.U-POE2; P/N: 116A00400S
C18 = 100nF,_10V,_X7R,_10%,_0402_19: CLABCONF0: FT.U-POE2; P/N: 151C22620S
C19 = 100nF,_10V,_X7R,_10%,_0402_13: CLABCONF0: FT.U-POE2; P/N: 151C22620S
C20 = 100nF,_10V,_X7R,_10%,_0402_3: CLABCONF0: FT.U-POE2; P/N: 151C22620S
C21 = 100nF,_10V,_X7R,_10%,_0402_14: CLABCONF0: FT.U-POE2; P/N: 151C22620S
C22 = 100nF,_10V,_X7R,_10%,_0402_11: CLABCONF0: FT.U-POE2; P/N: 151C22620S
C23 = 100nF,_10V,_X7R,_10%,_0402_4: CLABCONF0: FT.U-POE2; P/N: 151C22620S
C24 = 100nF,_10V,_X7R,_10%,_0402_6: CLABCONF0: FT.U-POE2; P/N: 151E47580S
C25 = 100nF,_10V,_X7R,_10%,_0402_9: CLABCONF0: FT.U-POE2; P/N: 151E47580S
C26 = 100nF,_10V,_X7R,_10%,_0402_10: CLABCONF0: FT.U-POE2; P/N: 151D22300S
C27 = 100nF,_10V,_X7R,_10%,_0402_18: CLABCONF0: FT.U-POE2; P/N: 151D18100S
C28 = 100nF,_10V,_X7R,_10%,_0402_15: CLABCONF0: FT.U-POE2; P/N: 151E47580S
C29 = 100nF,_10V,_X7R,_10%,_0402_20: CLABCONF0: FT.U-POE2; P/N: 151E47580S
C30 = 100nF,_10V,_X7R,_10%,_0402: CLABCONF0: FT.U-POE2; P/N: 151E10210S
C31 = 100nF,_10V,_X7R,_10%,_0402_16: CLABCONF0: FT.U-POE2; P/N: 151C10501S
C32 = 100nF,_10V,_X7R,_10%,_0402_17: CLABCONF0: FT.U-POE2; P/N: 151B22500S
C33 = 100nF,_10V,_X7R,_10%,_0402_2: CLABCONF0: FT.U-POE2; P/N: 151D56100S
C34 = 100nF,_10V,_X7R,_10%,_0402_1: CLABCONF0: FT.U-POE2; P/N: 151C47300S
C36 = 100nF,_10V,_X7R,_10%,_0402_21: CLABCONF0: FT.U-POE2; P/N: 151C47400S
C37 = 100nF,_10V,_X7R,_10%,_0402_8: CLABCONF0: FT.U-POE2; P/N: 151A22500S
C38 = 100nF,_10V,_X7R,_10%,_0402_12: CLABCONF0: FT.U-POE2; P/N: 151A22500S
C39 = 100nF,_10V,_X7R,_10%,_0402_7: CLABCONF0: FT.U-POE2; P/N: 151C10300S
D3 = Diode_,SBR12U100P5: CLABCONF0: FT.U-POE2; P/N: 130A10200S
D4 = BAT54WS: CLABCONF0: FT.U-POE2; P/N: 130A15100S
D5 = Diode_,SBR12U100P5_1: CLABCONF0: FT.U-POE2; P/N: 130B56001S
Q3 = FDMS7682: CLABCONF0: FT.U-POE2; P/N: 131D10130S
R47 = 0R_1: CLABCONF0: FT.U-POE2; P/N: 161C49R91S
R48 = 0R_17: CLABCONF0: FT.U-POE2; P/N: 161C56211S
R49 = 0R_10: CLABCONF0: FT.U-POE2; P/N: 161C20031S
R50 = 0R_3: CLABCONF0: FT.U-POE2; P/N: 161C16521S
R51 = 0R_7: CLABCONF0: FT.U-POE2; P/N: 161C11021S
R52 = 0R_4: CLABCONF0: FT.U-POE2; P/N: 161C35731S
R53 = 0R_12: CLABCONF0: FT.U-POE2; P/N: 161C11021S
R54 = 0R_8: CLABCONF0: FT.U-POE2; P/N: 161C2R205S
R55 = 0R_9: CLABCONF0: FT.U-POE2; P/N: 161C47511S
R56 = 0R_14: CLABCONF0: FT.U-POE2; P/N: 161HR0051S
R57 = 0R_16: CLABCONF0: NOP; P/N: 161C00005S
R58 = 0R_5: CLABCONF0: FT.U-POE2; P/N: 161C10045S
R59 = 0R_6: CLABCONF0: FT.U-POE2; P/N: 161C40221S
R60 = 0R_15: CLABCONF0: FT.U-POE2; P/N: 161C10021S
R61 = 0R: CLABCONF0: FT.U-POE2; P/N: 161C12131S
R62 = 0R_2: CLABCONF0: FT.U-POE2; P/N: 161C21531S
R63 = 0R_11: CLABCONF0: FT.U-POE2; P/N: 161C10021S
R64 = 0R_13: CLABCONF0: FT.U-POE2; P/N: 161C22111S
T1 = Power_transformer,_th: CLABCONF0: FT.U-POE2; P/N: 212A10020
TP2-TP4 TP6 TP7 TP9-TP11 = TestPoint_0: CLABCONF0: NOP; P/N: 188Z01380
U5 = MAX17690_Isolated_Flyback: CLABCONF0: FT.U-POE2; P/N: 123A60100S
U6 = LT3065_0: CLABCONF0: FT.U-POE2; P/N: 123M0R601S
C5 = 100nF,_10V,_X7R,_10%,_0402_1: CLABCONF0: FT.U-POE2; P/N: 151C10500S
C8 = 15pF,_50V,_NPO,_5%,_0402_3: CLABCONF0: FT.U-POE2; P/N: 151B10400S
P1 = M.2_Key-M_Generic_Bulk: CLABCONF0: FT.U-POE2; P/N: 182K06700S
R1 = 348R,1%,0402,1_16W_24: CLABCONF0: FT.U-POE2; P/N: 161C10011S
R2 = 348R,1%,0402,1_16W: CLABCONF0: FT.U-POE2; P/N: 161C00005S
R3 = 348R,1%,0402,1_16W_3: CLABCONF0: NOP; P/N: 161C00005S
R4 = 348R,1%,0402,1_16W_17: CLABCONF0: FT.U-POE2; P/N: 161C10011S
R5 = 348R,1%,0402,1_16W_21: CLABCONF0: NOP; P/N: 161C10011S
R6 = 348R,1%,0402,1_16W_10: CLABCONF0: NOP; P/N: 161C10011S
R7 = 348R,1%,0402,1_16W_8: CLABCONF0: FT.U-POE2; P/N: 161C10011S
R8 = 348R,1%,0402,1_16W_20: CLABCONF0: NOP; P/N: 161C10011S
R9 = 348R,1%,0402,1_16W_15: CLABCONF0: NOP; P/N: 161C10011S
R10 = 348R,1%,0402,1_16W_19: CLABCONF0: NOP; P/N: 161C10011S
R11 = 348R,1%,0402,1_16W_18: CLABCONF0: FT.U-POE2; P/N: 161C33R05S
R12 = 348R,1%,0402,1_16W_5: CLABCONF0: FT.U-POE2; P/N: 161C33R05S
R13 = 348R,1%,0402,1_16W_16: CLABCONF0: FT.U-POE2; P/N: 161C49R91S
R14 = 348R,1%,0402,1_16W_9: CLABCONF0: FT.U-POE2; P/N: 161C49R91S
R15 = 348R,1%,0402,1_16W_22: CLABCONF0: NOP; P/N: 161C00005S
R16 = 348R,1%,0402,1_16W_23: CLABCONF0: NOP; P/N: 161C00005S
R17 = 348R,1%,0402,1_16W_7: CLABCONF0: FT.U-POE2; P/N: 161C33R05S
R18 = 348R,1%,0402,1_16W_13: CLABCONF0: FT.U-POE2; P/N: 161C33R05S
R19 = 348R,1%,0402,1_16W_6: CLABCONF0: FT.U-POE2; P/N: 161C49R91S
R20 = 348R,1%,0402,1_16W_12: CLABCONF0: FT.U-POE2; P/N: 161C49R91S
R21 = 348R,1%,0402,1_16W_2: CLABCONF0: FT.U-POE2; P/N: 161C49R91S
R22 = 348R,1%,0402,1_16W_4: CLABCONF0: FT.U-POE2; P/N: 161C49R91S
R23 = 348R,1%,0402,1_16W_11: CLABCONF0: NOP; P/N: 161C10011S
R24 = 348R,1%,0402,1_16W_1: CLABCONF0: FT.U-POE2; P/N: 161C47501S
R25 = 348R,1%,0402,1_16W_14: CLABCONF0: FT.U-POE2; P/N: 161C10011S
U1 = 24C02,_serial_EE,_2KB,_I2C: CLABCONF0: FT.U-POE2; P/N: 111S31000S
U2 = Clock_1-__2,_PCIe_Gen_2: CLABCONF0: FT.U-POE2; P/N: 106IA1010S

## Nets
+0V9LAN1: C40.1 C55.1 C61.1 C77.2 C81.1 U7.11(VDD0p9) U7.32(VDD0p9) U7.38(VDD0p9_OUT) U7.42(VDD0p9) U7.59(VDD0p9)
+0V9LAN2: C82.1 C92.1 C97.1 C112.2 C119.1 U9.11(VDD0p9) U9.32(VDD0p9) U9.38(VDD0p9_OUT) U9.42(VDD0p9) U9.59(VDD0p9)
+1V5LAN1: C56.1 C74.1 C79.2 U7.39(VDD1p5_OUT) U7.47(VDD1p5) U7.56(VDD1p5)
+1V5LAN2: C93.1 C109.1 C117.2 U9.39(VDD1p5_OUT) U9.47(VDD1p5) U9.56(VDD1p5)
+3V3_EP: P1.28(3V3EEPROM) R2.1
+3V3_EP_R: C2.2 R2.2 R3.2 R4.1 R5.1 R6.1 U1.8(VCC)
+3V3ISO: C10.1 C12.1 C14.2 R31.1 R32.1 R33.1 R35.1 R39.1 U3.13(VDD) U4.12(VISO) U4.17(VDDISO)
+3V3LAN: C37.2 C38.2 C41.1 C42.2 C49.1 C50.2 C59.2 C60.1 C66.1 C71.1 C76.1 C80.1 C83.1 C84.2 C85.1 C86.2 C95.2 C96.1 C102.1 C107.1 C115.1 C118.1 P2.A9(LED2_A) P2.A11(LED1_A) P2.B9(LED2_A) P2.B11(LED1_A) R57.1 R63.1 R66.1 R67.1 R68.1 R77.1 R78.1 R79.1 RN1.5(RD2) RN1.7(RB2) RN1.8(RA2) RN2.7(RB2) RN2.8(RA2) RN3.5(RD2) RN3.7(RB2) RN3.8(RA2) RN4.7(RB2) RN4.8(RA2) TP12.1 U6.9(VOUT) U6.10(VOUT) U7.1(LAN_PWRGD) U7.10(VDD3p3) U7.27(VDD3p3) U7.41(VDD3p3) U7.51(VDD3p3) U7.64(VDD3p3) U9.1(LAN_PWRGD) U9.10(VDD3p3) U9.27(VDD3p3) U9.41(VDD3p3) U9.51(VDD3p3) U9.64(VDD3p3)
+3V3S: C3.2 C4.2 C5.2 C6.2 C7.2 C8.2 P1.56(3V3S) P1.58(3V3S) P1.68(3V3S) P1.70(3V3S) P1.72(3V3S) P1.74(3V3S) R3.1 R7.1 R23.1 R26.2 R57.2 U2.5(VDD) U2.9(VDD) U2.12(VDD) U2.16(VDD) U2.20(VDDA)
+5VA: C1.2 C13.2 C35.2 P1.1(5VA) P1.2(5VA) P1.4(5VA) P1.6(5VA) P1.8(5VA) P1.10(5VA) P1.12(5VA) P1.14(5VA) P1.16(5VA) P1.18(5VA) P1.20(5VA) R27.2 U4.9(VIN) U6.1(VIN) U6.2(VIN) U6.3(SHD#)
+VIN: C18.2 C19.2 C20.2 C21.2 C22.2 C23.2 C26.2 C31.2 R47.1 R48.1 R49.1 TP2.1 TP6.1 U5.3(VIN)
+VIN_T: T1.4 T1.5 TP3.1
-VEE: C17.1 C24.1 C25.1 C28.1 C29.1 C30.1 D5.ANODE R40.1 R42.1 TP11.1 U3.19(SENSE4) U3.22(SENSE3) U3.25(VEE) U3.26(VEE) U3.39(PAD_(VEE))
-VEE_T: T1.9 T1.10 TP10.1
GND: C1.1 C2.1 C3.1 C4.1 C5.1 C6.1 C7.1 C8.1 C9.2 C13.1 C18.1 C19.1 C20.1 C21.1 C22.1 C23.1 C30.2 C31.1 C32.2 C33.1 C34.1 C35.1 C36.2 C37.1 C38.1 C39.1 C40.2 C41.2 C42.1 C43.2 C44.2 C45.1 C46.1 C49.2 C50.1 C55.2 C56.2 C59.1 C60.2 C61.2 C66.2 C67.1 C68.1 C69.1 C70.1 C71.2 C74.2 C75.1 C76.2 C77.1 C78.1 C79.1 C80.2 C81.2 C82.2 C83.2 C84.1 C85.2 C86.1 C92.2 C93.2 C95.1 C96.2 C97.2 C102.2 C103.1 C104.1 C105.1 C106.1 C107.2 C109.2 C111.1 C112.1 C115.2 C116.1 C117.1 C118.2 C119.2 P1.3(GND) P1.9(GND) P1.15(GND) P1.21(GND) P1.27(GND) P1.33(GND) P1.39(GND) P1.45(GND) P1.46(GND) P1.50(GND) P1.51(GND) P1.57(GND) P1.71(GND) R1.2 R8.2 R9.2 R10.2 R13.1 R14.1 R19.1 R20.1 R21.1 R22.1 R24.2 R25.2 R51.2 R56.2 R58.2 R59.2 R60.2 R61.2 R62.2 R64.2 R75.2 R86.2 RN1.6(RC2) RN2.5(RD2) RN2.6(RC2) RN3.6(RC2) RN4.5(RD2) RN4.6(RC2) TP7.1 U1.4(GND) U2.6(GND) U2.15(GND) U2.19(GNDA) U4.1(GNDP) U4.5(GNDP) U4.7(GNDP) U4.8(PDIS) U4.10(GNDP) U5.12(SGND) U5.14(PGND) U5.17(PAD-SGND) U6.5(IMAX) U6.7(GND) U6.11(GND) U7.65(EPAD-GND) U9.65(EPAD-GND) X1.2(GND) X1.4(GND) X2.2(GND) X2.4(GND)
GND_ISO: C10.2 C11.2 C12.2 C14.1 C15.1 C16.1 C17.2 C24.2 C25.2 C28.2 C29.2 C64.2 C100.2 D1.3(CATHODE) D2.3(CATHODE) D3.3(CATHODE) D5.CATHODE R36.2 R37.2 R38.2 R41.2 R43.2 R44.2 R45.2 R46.2 U3.10(DGND) U3.18(AGND) U4.11(GNDISO) U4.14(GNDISO) U4.16(GNDISO) U4.20(GNDISO) U8.30(MCT7) U8.42(MCT3)
V33LDO_FB: R63.2 R64.1 U6.8(ADJ)
V33LDO_SS: C39.2 U6.6(REF/BP)
CHASSIS_ETH: C43.1 C44.1 C45.2 C46.2 C73.2 C110.2 P2.SH1(SHIELD) P2.SH2(SHIELD)
CLK_PCIE_0N: R12.2 R13.2 U7.25(PECLKn)
CLK_PCIE_0N_R: R12.1 U2.8(PCIEXC0)
CLK_PCIE_0P: R11.2 R14.2 U7.26(PECLKp)
CLK_PCIE_0P_R: R11.1 U2.7(PCIEXT0)
CLK_PCIE_1N: R18.2 R21.2 U9.25(PECLKn)
CLK_PCIE_1N_R: R18.1 U2.13(PCIEXC1)
CLK_PCIE_1P: R17.2 R22.2 U9.26(PECLKp)
CLK_PCIE_1P_R: R17.1 U2.14(PCIEXT1)
CLK_PCIE_N: P1.53(PCIE_CLKN) R20.2 U2.3(CLK_INC)
CLK_PCIE_P: P1.55(PCIE_CLKP) R19.2 U2.2(CLK_INT)
CLKMP_IREF: R24.1 U2.18(IREF)
CLKMP_PLL_BW: R23.2 R25.1 U2.1(PLL_BW)
CLKREQ#: P1.26(CLKREQ#) R1.1
EEPROM_A0: R6.2 R10.1 U1.1(A0)
EEPROM_A1: R5.2 R9.1 U1.2(A1)
EEPROM_A2: R4.2 R8.1 U1.3(A2)
ISO_VDDP: C9.1 R26.1 R27.1 R28.1 R29.1 U4.4(VDDP)
ISO_VSEL: R35.2 R36.1 U4.13(VSEL)
LAN1_CBOT: C72.1 U7.37(CBOT)
LAN1_CTOP: C72.2 U7.40(CTOP)
LAN1_DEV_OFF#: R68.2 U7.28(DEV_OFF_N)
LAN1_LED1: R69.1 U7.30(LED1)
LAN1_LED1_C: P2.A12(LED1_C) R69.2
LAN1_LED2: R70.1 U7.31(LED0)
LAN1_LED2_C: P2.A10(LED2_C) R70.2
LAN1_MDI0N: U7.57(MDI_N[0]) U8.23(TD8+)
LAN1_MDI0N_T: P2.A2(MDI0-) U8.26(MX8+)
LAN1_MDI0P: U7.58(MDI_P[0]) U8.24(TD8-)
LAN1_MDI0P_T: P2.A1(MDI0+) U8.25(MX8-)
LAN1_MDI1N: U7.54(MDI_N[1]) U8.20(TD7+)
LAN1_MDI1N_T: P2.A6(MDI1-) U8.29(MX7+)
LAN1_MDI1P: U7.55(MDI_P[1]) U8.21(TD7-)
LAN1_MDI1P_T: P2.A3(MDI1+) U8.28(MX7-)
LAN1_MDI2N: U7.52(MDI_N[2]) U8.17(TD6+)
LAN1_MDI2N_T: P2.A5(MDI2-) U8.32(MX6+)
LAN1_MDI2P: U7.53(MDI_P[2]) U8.18(TD6-)
LAN1_MDI2P_T: P2.A4(MDI2+) U8.31(MX6-)
LAN1_MDI3N: U7.49(MDI_N[3]) U8.14(TD5+)
LAN1_MDI3N_T: P2.A8(MDI3-) U8.35(MX5+)
LAN1_MDI3P: U7.50(MDI_P[3]) U8.15(TD5-)
LAN1_MDI3P_T: P2.A7(MDI3+) U8.34(MX5-)
LAN1_NCSI_PD1: RN1.3(RC1) U7.7(NCSI_TX_EN_/_PD)
LAN1_NCSI_PD2: RN2.3(RC1) U7.3(NCSI_CRS_DV_/_PD)
LAN1_NCSI_PD3: RN2.4(RD1) U7.2(NCSI_CLK_/_PD)
LAN1_NCSI_PU1: RN1.1(RA1) U7.9(NCSI_TXD0_/_PU)
LAN1_NCSI_PU2: RN1.2(RB1) U7.8(NCSI_TXD1_/_PU)
LAN1_NCSI_PU3: RN1.4(RD1) U7.6(NCSI_RXD0_/_PU)
LAN1_NCSI_PU4: RN2.1(RA1) U7.5(NCSI_RXD1_/_PU)
LAN1_RSET: R75.1 U7.48(RSET)
LAN1_TCK: R66.2 U7.19(JTAG_CLK)
LAN1_TDO: RN2.2(RB1) U7.4(JTAG_TDO)
LAN1_TMS: R67.2 U7.18(JTAG_TMS)
LAN1_XTAL1: C75.2 U7.46(XTAL1) X1.1
LAN1_XTAL2: C78.2 U7.45(XTAL2) X1.3
LAN2_CBOT: C108.1 U9.37(CBOT)
LAN2_CTOP: C108.2 U9.40(CTOP)
LAN2_DEV_OFF#: R79.2 U9.28(DEV_OFF_N)
LAN2_LED1: R80.1 U9.30(LED1)
LAN2_LED1_C: P2.B12(LED1_C) R80.2
LAN2_LED2: R81.1 U9.31(LED0)
LAN2_LED2_C: P2.B10(LED2_C) R81.2
LAN2_MDI0N: U8.11(TD4+) U9.57(MDI_N[0])
LAN2_MDI0N_T: P2.B2(MDI0-) U8.38(MX4+)
LAN2_MDI0P: U8.12(TD4-) U9.58(MDI_P[0])
LAN2_MDI0P_T: P2.B1(MDI0+) U8.37(MX4-)
LAN2_MDI1N: U8.8(TD3+) U9.54(MDI_N[1])
LAN2_MDI1N_T: P2.B6(MDI1-) U8.41(MX3+)
LAN2_MDI1P: U8.9(TD3-) U9.55(MDI_P[1])
LAN2_MDI1P_T: P2.B3(MDI1+) U8.40(MX3-)
LAN2_MDI2N: U8.5(TD2+) U9.52(MDI_N[2])
LAN2_MDI2N_T: P2.B5(MDI2-) U8.44(MX2+)
LAN2_MDI2P: U8.6(TD2-) U9.53(MDI_P[2])
LAN2_MDI2P_T: P2.B4(MDI2+) U8.43(MX2-)
LAN2_MDI3N: U8.2(TD1+) U9.49(MDI_N[3])
LAN2_MDI3N_T: P2.B8(MDI3-) U8.47(MX1+)
LAN2_MDI3P: U8.3(TD1-) U9.50(MDI_P[3])
LAN2_MDI3P_T: P2.B7(MDI3+) U8.46(MX1-)
LAN2_NCSI_PD1: RN3.3(RC1) U9.7(NCSI_TX_EN_/_PD)
LAN2_NCSI_PD2: RN4.3(RC1) U9.3(NCSI_CRS_DV_/_PD)
LAN2_NCSI_PD3: RN4.4(RD1) U9.2(NCSI_CLK_/_PD)
LAN2_NCSI_PU1: RN3.1(RA1) U9.9(NCSI_TXD0_/_PU)
LAN2_NCSI_PU2: RN3.2(RB1) U9.8(NCSI_TXD1_/_PU)
LAN2_NCSI_PU3: RN3.4(RD1) U9.6(NCSI_RXD0_/_PU)
LAN2_NCSI_PU4: RN4.1(RA1) U9.5(NCSI_RXD1_/_PU)
LAN2_RSET: R86.1 U9.48(RSET)
LAN2_TCK: R77.2 U9.19(JTAG_CLK)
LAN2_TDO: RN4.2(RB1) U9.4(JTAG_TDO)
LAN2_TMS: R78.2 U9.18(JTAG_TMS)
LAN2_XTAL1: C111.2 U9.46(XTAL1) X2.1
LAN2_XTAL2: C116.2 U9.45(XTAL2) X2.3
MCT1C: C65.1 R74.2
MCT2C: C64.1 R73.2
MCT3: C63.2 U8.33(MCT6)
MCT3C: C63.1 R72.2
MCT4: C62.2 U8.36(MCT5)
MCT4C: C62.1 R71.2
MCT5C: C101.1 R85.2
MCT6C: C100.1 R84.2
MCT7: C99.2 U8.45(MCT2)
MCT7C: C99.1 R83.2
MCT8: C98.2 U8.48(MCT1)
MCT8C: C98.1 R82.2
MCT_CMN1: C73.1 R71.1 R72.1 R73.1 R74.1
MCT_CMN2: C110.1 R82.1 R83.1 R84.1 R85.1
PCIE0_RXN: C51.2 P1.43(PCIE_RX0P)
PCIE0_RXN_C: C51.1 U7.20(PE_Tn)
PCIE0_RXP: C52.2 P1.41(PCIE_RX0N)
PCIE0_RXP_C: C52.1 U7.21(PE_Tp)
PCIE0_TXN: C57.2 P1.49(PCIE_TX0P)
PCIE0_TXN_C: C57.1 U7.23(PE_Rn)
PCIE0_TXP: C58.2 P1.47(PCIE_TX0N)
PCIE0_TXP_C: C58.1 U7.24(PE_Rp)
PCIE1_RXN: C88.2 P1.31(PCIE_RX1P)
PCIE1_RXN_C: C88.1 U9.20(PE_Tn)
PCIE1_RXP: C90.2 P1.29(PCIE_RX1N)
PCIE1_RXP_C: C90.1 U9.21(PE_Tp)
PCIE1_TXN: C91.2 P1.37(PCIE_TX1P)
PCIE1_TXN_C: C91.1 U9.23(PE_Rn)
PCIE1_TXP: C94.2 P1.35(PCIE_TX1N)
PCIE1_TXP_C: C94.1 U9.24(PE_Rp)
PCIE_WAKE_LAN1: R65.2 U7.16(PE_WAKE_N)
PCIE_WAKE_LAN2: R76.2 U9.16(PE_WAKE_N)
PE_WAKE#: P1.22(PCIE_WAKE#) R65.1 R76.1
PLTRST#: P1.24(RESET#) U7.17(PE_RST_N) U9.17(PE_RST_N)
POE_AD0: R43.1 U3.7(AD0)
POE_AD1: R44.1 U3.6(AD1)
POE_AD2: R45.1 U3.5(AD2)
POE_AD3: R46.1 U3.4(AD3)
POE_AUTO: R39.2 R41.1 U3.33(AUTO)
POE_GATE1: Q2.4(G) U3.31(GATE1)
POE_GATE2: Q1.4(G) U3.28(GATE2)
POE_INT#: TP1.1 U3.37(INT#)
POE_RESET#: C11.1 R33.2 U3.35(RESET#)
POE_SCL: R31.2 U3.38(SCL) U4.19(SCL1)
POE_SDA: R32.2 U3.1(SDAOUT) U3.3(SDAIN) U4.18(SDA1)
POE_SENSE1: Q2.1(S1) Q2.2(S2) Q2.3(S3) R42.2 U3.30(SENSE1)
POE_SENSE2: Q1.1(S1) Q1.2(S2) Q1.3(S3) R40.2 U3.27(SENSE2)
POE_SHDN3#: R37.1 U3.16(SHDN3#)
POE_SHDN4#: R38.1 U3.17(SHDN4#)
SATAXPCIE: P1.36(PCIE_SATA#) R7.2
SMB_CLK: P1.48(SMB_CLK) R16.1 R30.2 U1.6(SCL)
SMB_CLK_CLKMP: R16.2 U2.11(SMBCLK)
SMB_CLK_R: R28.2 R30.1 U4.2(SCL2)
SMB_DATA: P1.42(SMB_DATA) R15.1 R34.2 U1.5(SDA)
SMB_DATA_CLKMP: R15.2 U2.10(SMBDAT)
SMB_DATA_R: R29.2 R34.1 U4.3(SDA2)
TCT1: C67.2 U8.22(TCT8)
TCT2: C68.2 U8.19(TCT7)
TCT3: C69.2 U8.16(TCT6)
TCT4: C70.2 U8.13(TCT5)
TCT5: C103.2 U8.10(TCT4)
TCT6: C104.2 U8.7(TCT3)
TCT7: C105.2 U8.4(TCT2)
TCT8: C106.2 U8.1(TCT1)
V_PoE_1: C16.2 C65.2 D2.1(ANODE1) D2.2(ANODE2) Q2.5(D4) Q2.6(D3) Q2.7(D2) Q2.8(D1) U3.32(OUT1) U8.27(MCT8)
V_PoE_2: C15.2 C101.2 D1.1(ANODE1) D1.2(ANODE2) Q1.5(D4) Q1.6(D3) Q1.7(D2) Q1.8(D1) U3.29(OUT2) U8.39(MCT4)
VE_COMP: C33.2 R55.2 U5.9(COMP)
VE_COMP_R: C34.2 R55.1
VE_CS: Q3.1(S1) Q3.2(S2) Q3.3(S3) R56.1 U5.13(CS)
VE_EN_ULVO: R49.2 R50.1 U5.2(EN/UVLO)
VE_FB: R52.1 U5.4(FB)
VE_FB_R: R52.2 R53.1
VE_GND_SEC: D3.1(ANODE1) D3.2(ANODE2)
VE_GND_SEC_T: T1.7 T1.8 TP4.1
VE_INTVCC: C32.1 U5.16(INTVCC)
VE_LX: C27.1 D4.ANODE Q3.5(D1) Q3.6(D2) Q3.7(D3) Q3.8(D4) R53.2
VE_LX_C: C27.2 R47.2
VE_LX_T: T1.1 T1.2 TP9.1
VE_NDRV: R54.1 U5.15(NDRV)
VE_NDRV_R: Q3.4(G) R54.2
VE_OVI: R50.2 R51.1 U5.1(OVI)
VE_RIN: R62.1 U5.8(RIN)
VE_RT: R59.1 U5.11(RT)
VE_SET: R60.1 U5.5(SET)
VE_SNUB: C26.1 D4.CATHODE R48.2
VE_SS: C36.1 U5.10(SS)
VE_TC: R58.1 U5.6(TC)
VE_VCM: R61.1 U5.7(VCM)

Not connected (* = marked no-connect by the designer): P1 5(PCIE_RX3N)* 7(PCIE_RX3P)* 11(PCIE_TX3N)* 13(PCIE_TX3P)* 17(PCIE_RX2N)* 19(PCIE_RX2P)* 23(PCIE_TX2N)* 25(PCIE_TX2P)* 30(RIBBON_ID1)* 32(RIBBON_ID2)* 34(RIBBON_ID3)* 38(RSVD)* 40(RIBBON_ID4)* 44(SMB_ALERT#)* 52(Diff._RSVD1_N)* 54(Diff._RSVD1_P)* 67(Diff._RSVD2_N)* 69(Diff._RSVD2_P)* 73(USB2_N)* 75(USB2_P)*; T1 3* 6*; U1 7(WP)*; U2 4(vCLKREQ0#)* 17(vCLKREQ1#)*; U3 2(NC)* 8(DNC)* 9(NC)* 11(NC)* 12(NC)* 14(SHDN1#)* 15(SHDN2#)* 20(GATE4)* 21(OUT4)* 23(GATE3)* 24(OUT3)* 34(MSD#)* 36(MID)*; U4 6(NC)* 15(NC)*; U6 4(PWRGD)*; U7 12(NVM_SI_/_PU)* 13(NVM_SK_/_PU)* 14(NVM_SO_/_PU)* 15(NVM_CS_N_/_PU)* 22(NC)* 29(JTAG_TDI)* 33(LED2)* 34(SMB_CLK_/_PU)* 35(SMB_ALRT_N_/_PU)* 36(SMB_DAT_/_PU)* 43(NCSI_ARB_IN)* 44(NCSI_ARB_OUT)* 60(SDP3)* 61(SDP1[PCIe_DIS])* 62(SDP2)* 63(SDP0)*; U9 12(NVM_SI_/_PU)* 13(NVM_SK_/_PU)* 14(NVM_SO_/_PU)* 15(NVM_CS_N_/_PU)* 22(NC)* 29(JTAG_TDI)* 33(LED2)* 34(SMB_CLK_/_PU)* 35(SMB_ALRT_N_/_PU)* 36(SMB_DAT_/_PU)* 43(NCSI_ARB_IN)* 44(NCSI_ARB_OUT)* 60(SDP3)* 61(SDP1[PCIe_DIS])* 62(SDP2)* 63(SDP0)*

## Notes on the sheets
sheet 1
- INDEX
- PAGE
- DESCRIPTION
- FT.U-POE2 1.1
- 01
- Index
- 02
- TRIP connector, EEPROM, CLK Multiplier
- 03
- POE Controller
- 04
- Power
- 05
- Lan 1 controlle + connector
- 06
- Lan 2 controlle + connector
- BOARD REVISION HISTORY
- BOARD REVISION: 1.0
- - INITIAL REVISION
- BOARD REVISION: 1.1
- - ADDED TO BOM:
    LABEL -         374F08P08C
    YELLOW LATCH -  290E010010
  - FIXED ETH CONNECTOR PINOUT
  - ADDED ZENER FOR VOLTAGE LIMIT AT LOW LOAD
  -Changed PoE controller PN to Type 1 controller
- Wires to TP6 and TP7
- Qty = 0.25 (m)
- Qty = 0.25 (m)
sheet 2
- Standard TRIP
- NOP
- EEPROM
- NOP
- NOP
- No CLKREQ support in I210
- Polarity swap x4
- High -> PCIe
- SMB:0x54
- NOP
- NOP
- NOP
- CLOCK Multiplier
- Internal 120K PD
- Internal 120K PD
- NOP
- NOP
sheet 3
- PoE Controller
- NOP
- NOP
- NOP
- Up to 30mA out
- NOP
- 1.23V
- Int. PU
- 4x Int. PU
- Int. PD
- NOP
- 4x Int. PU
- SMB Addr.: 010[A3][A2][A1][A0]b
               + 0110000b (30h)
  - 0x2F
- NOP
- NOP
- NOP
- NOP
- PoE controller changed at rev. 1.1
sheet 4
- Isolated 54V
- VIN = 10V - 22.7V
- Solder pin
- VIN = 10V - 22.7V
- Solder pin
- PIN VOL.:
- 1.215V
- 1.1V
- Transformer PCB
- EN/ULVO
- VIN=10V
- VIN=9.1V
- OVI
- VIN=25.1V
- VIN=22.7V
- Design based on MAXREFDES1040
- Zener for voltage limitation at low load
- Rev. 1.0: D5 is hand stitched
- 3.3V , 500mA
- F(sw) = 124KHz
- NOP
- RIN=0.6*R(FB)
- 0.6V
- F(sw)<=160KHz
  (according to 10V<VIN<25V)
- Using +5VA as a source in order to enable wake on LAN
sheet 5
- LAN1 - I210
- at least 20 mil split
- pin numbers change at rev. 1.1
- 100nF caps for non-gen 3 PCIe
sheet 6
- LAN2 - I210
- pin numbers change at rev. 1.1
- 100nF caps for non-gen 3 PCIe
